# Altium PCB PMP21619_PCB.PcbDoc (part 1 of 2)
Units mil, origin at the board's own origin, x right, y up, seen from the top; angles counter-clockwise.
Board outline 3937.01 x 3937.01 mil, 8 copper layers (Top Layer, Signal Layer 1, Signal Layer 2, Signal Layer 3, Signal Layer 4, Signal Layer 5, Signal Layer 6, Bottom Layer), stack 62.283 mil thick; 227 components, 41 nets, 547 pads, 421 vias.
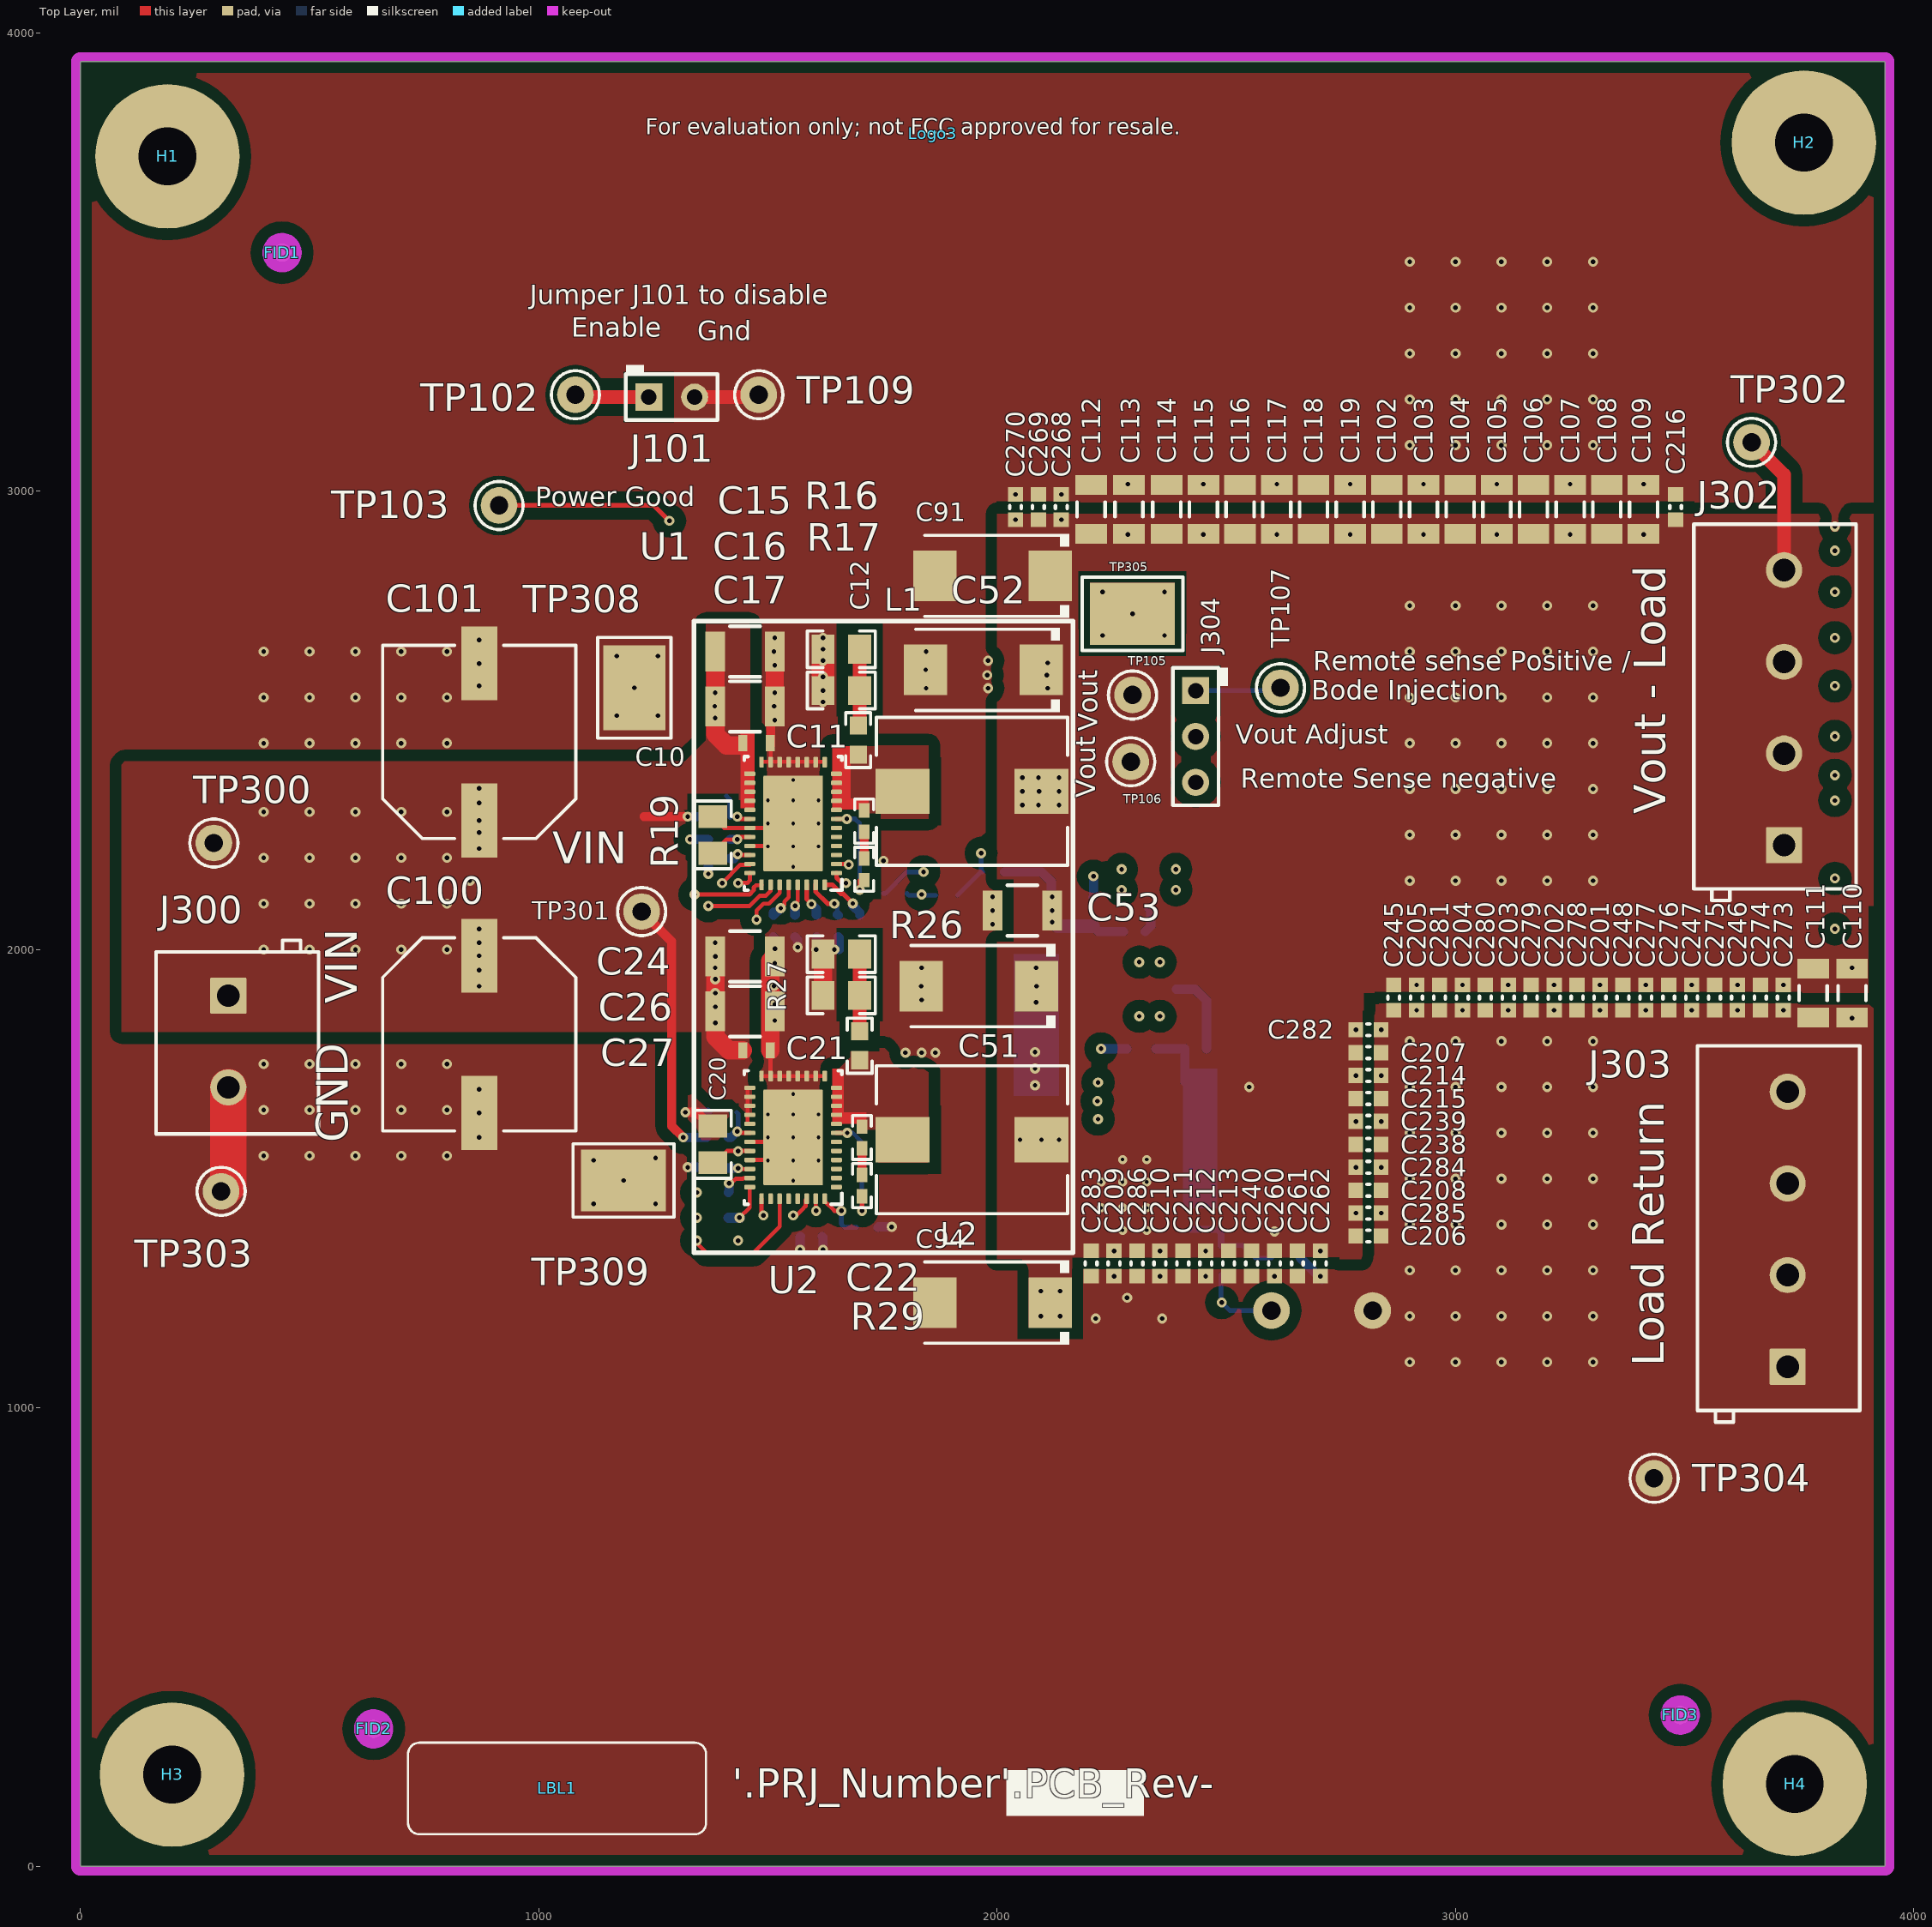
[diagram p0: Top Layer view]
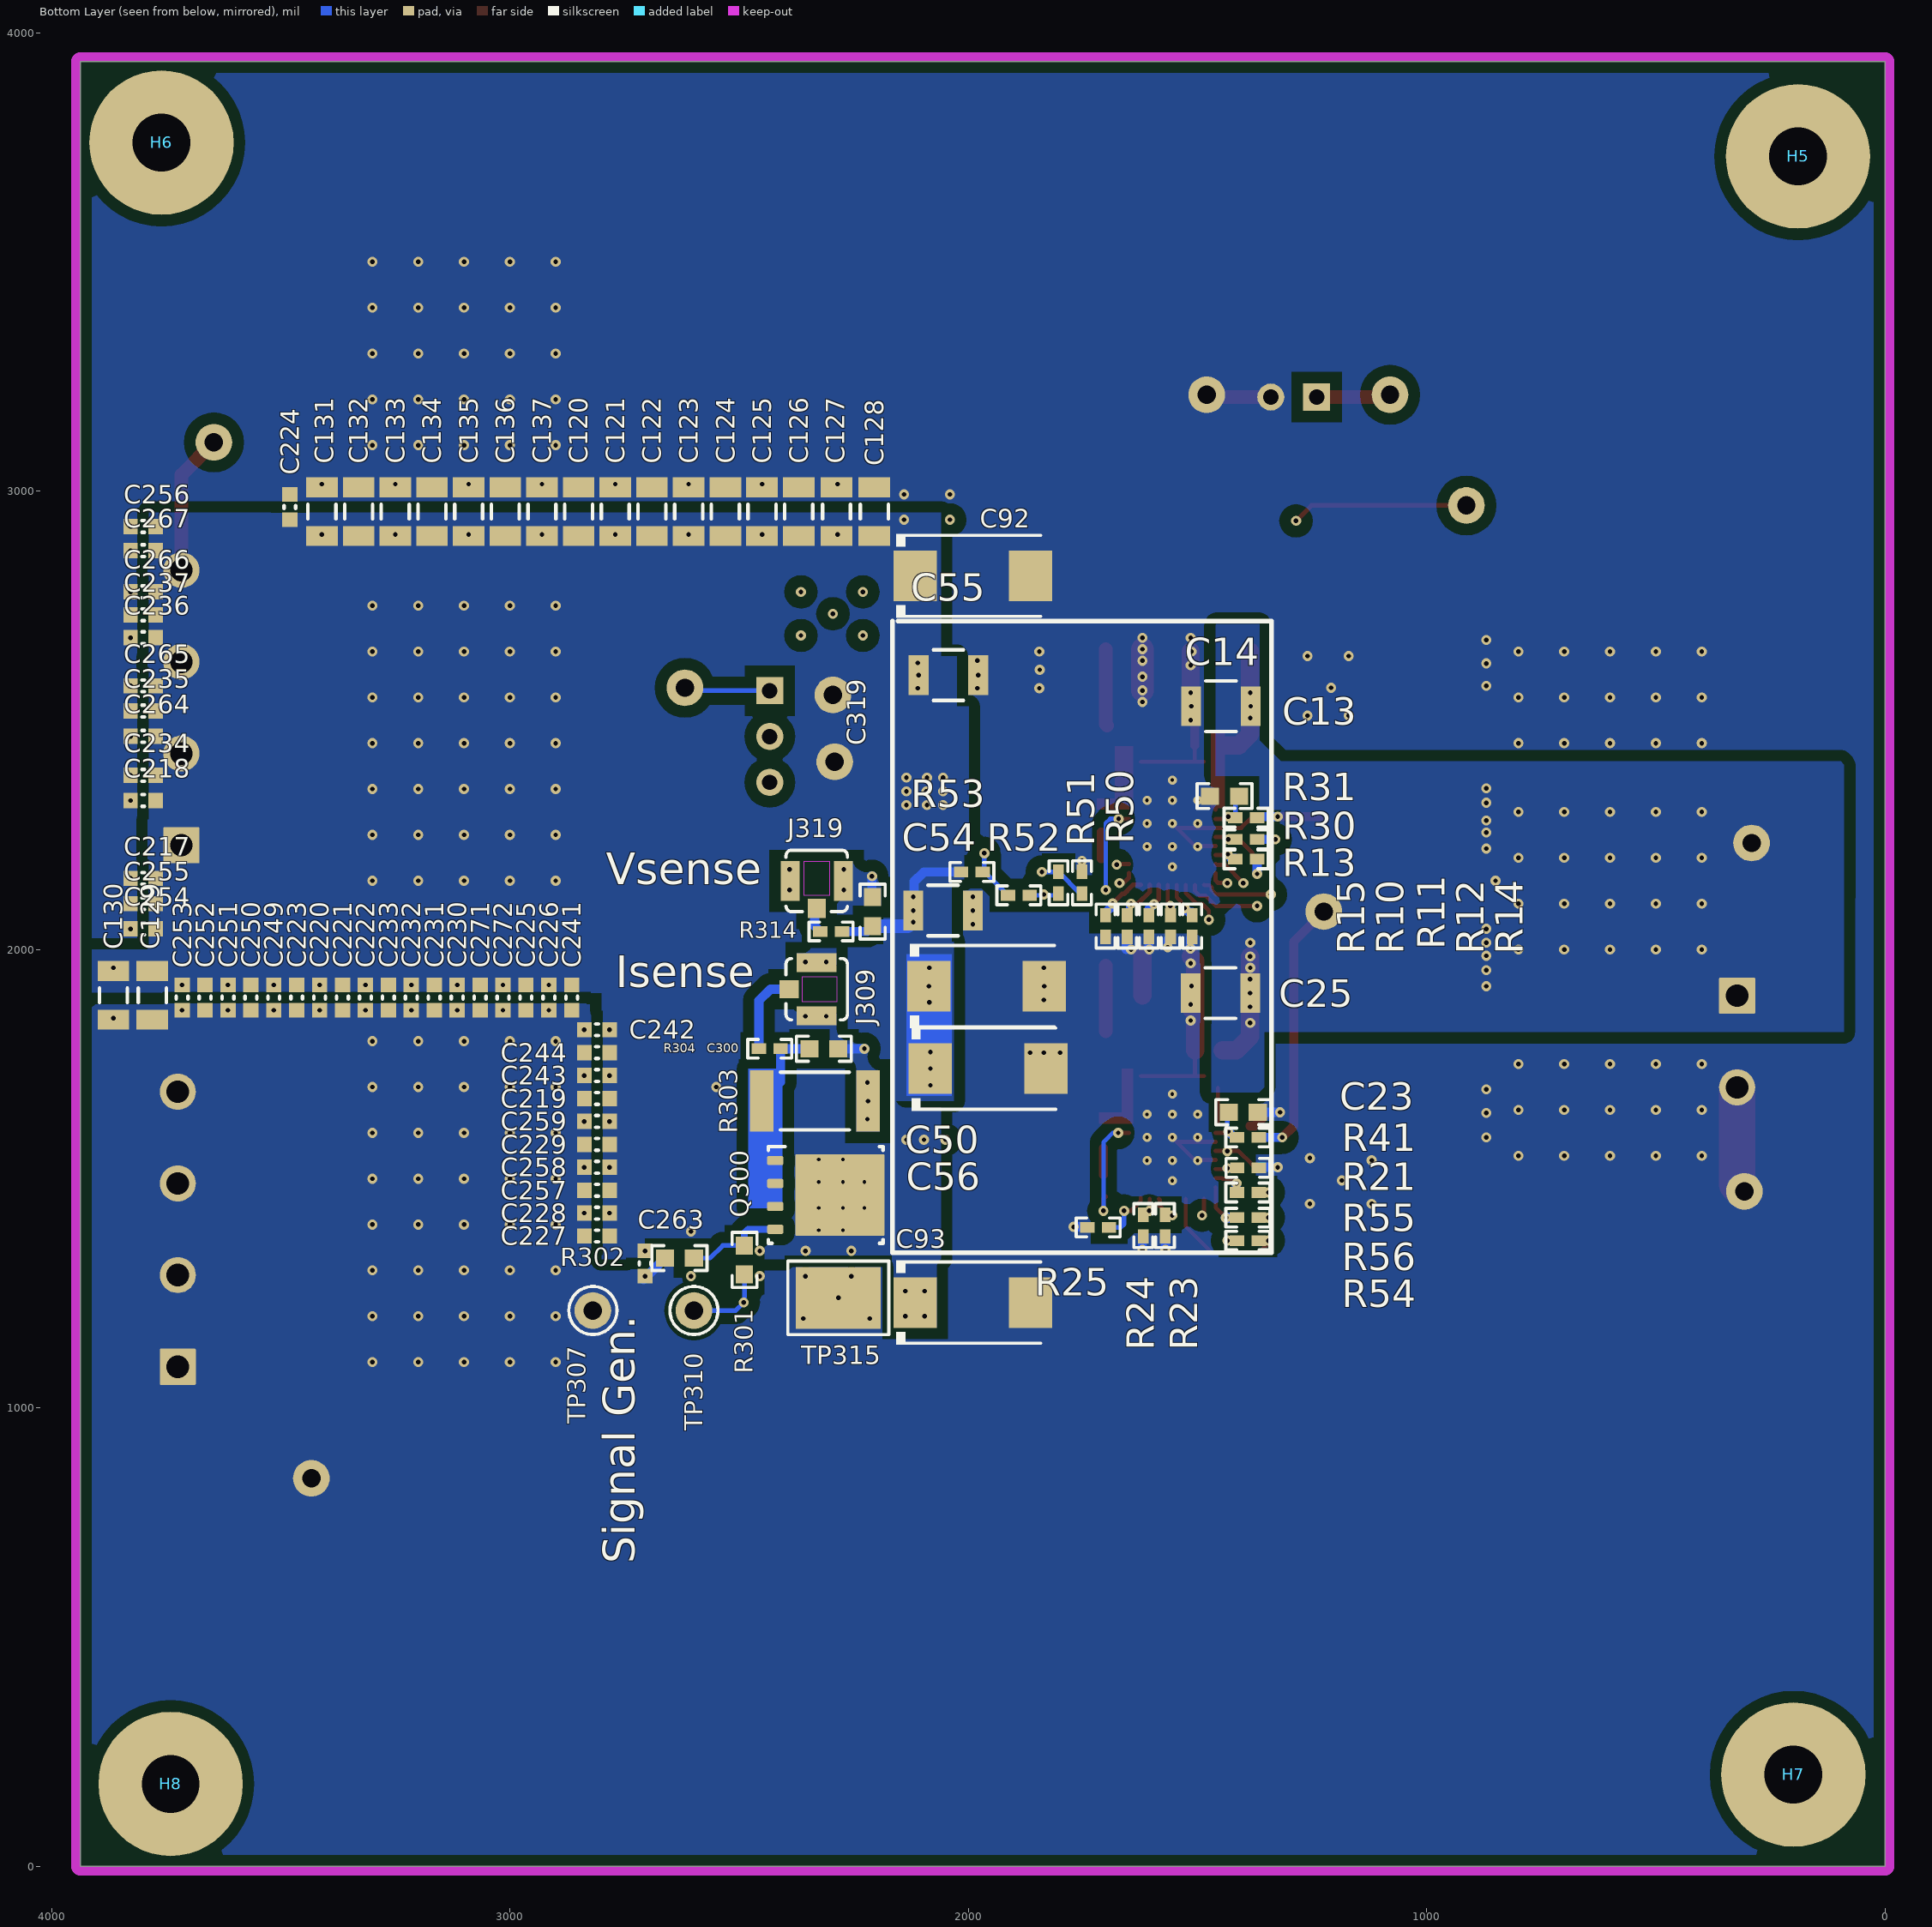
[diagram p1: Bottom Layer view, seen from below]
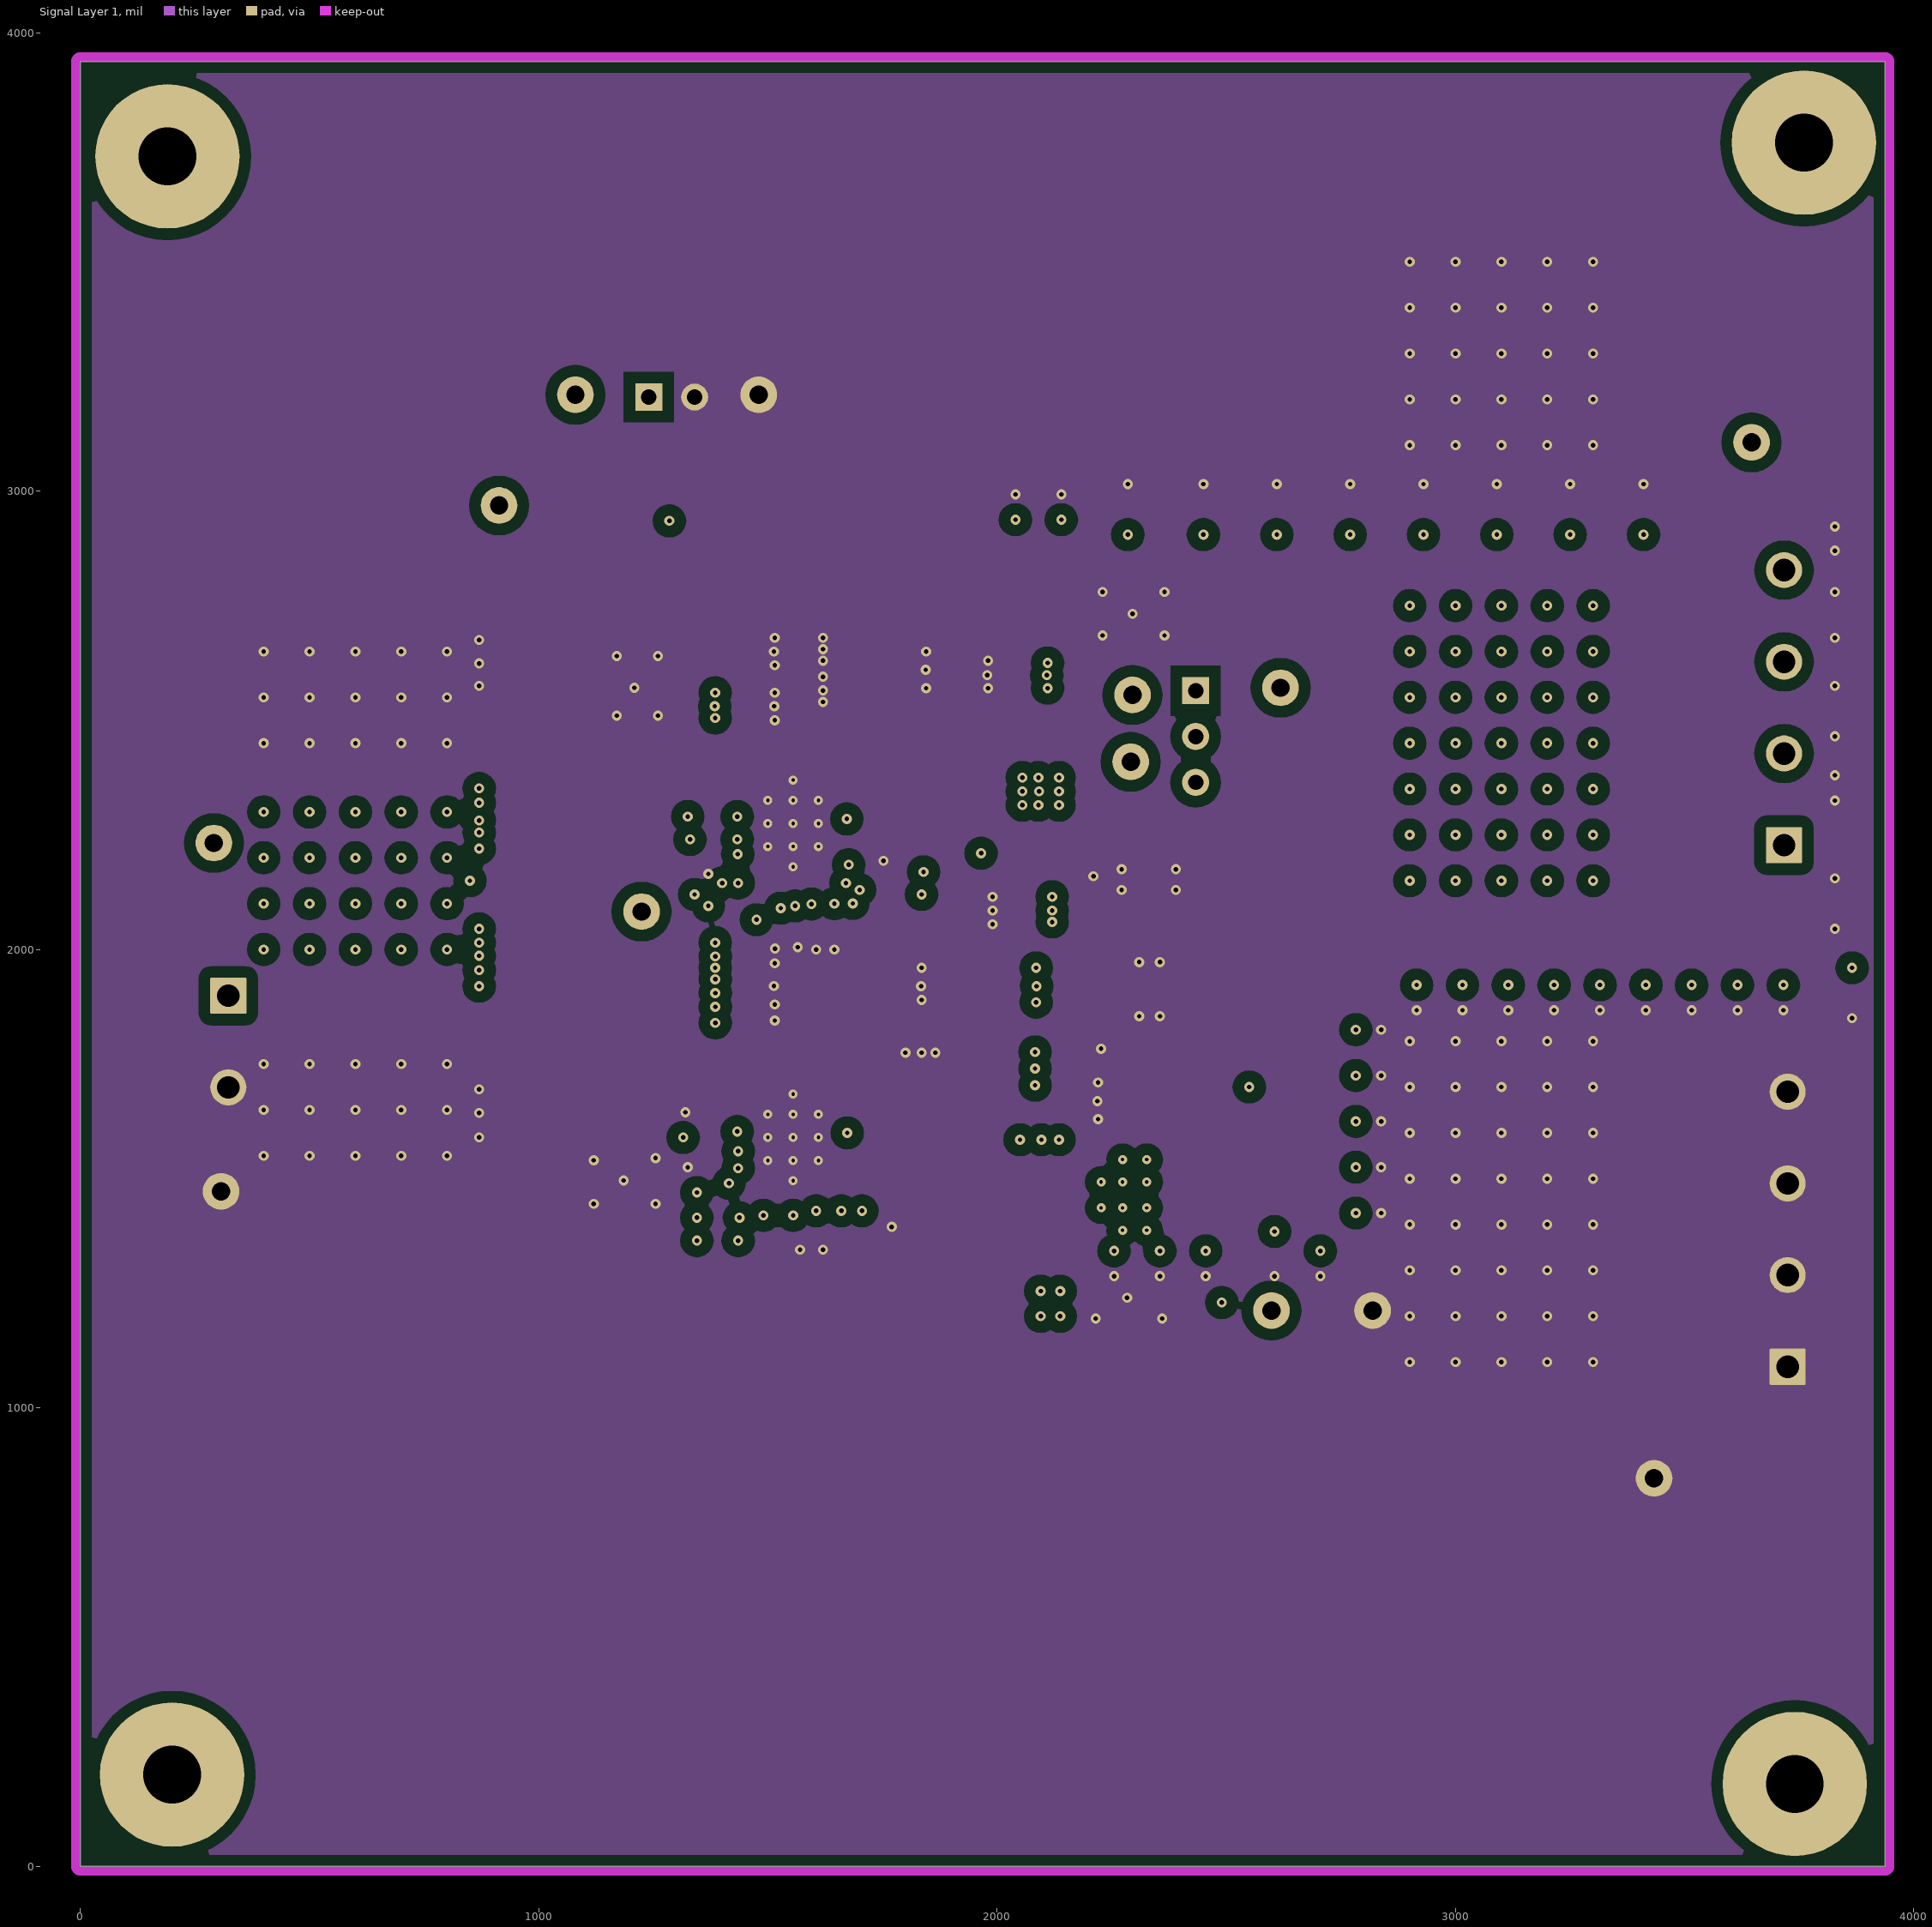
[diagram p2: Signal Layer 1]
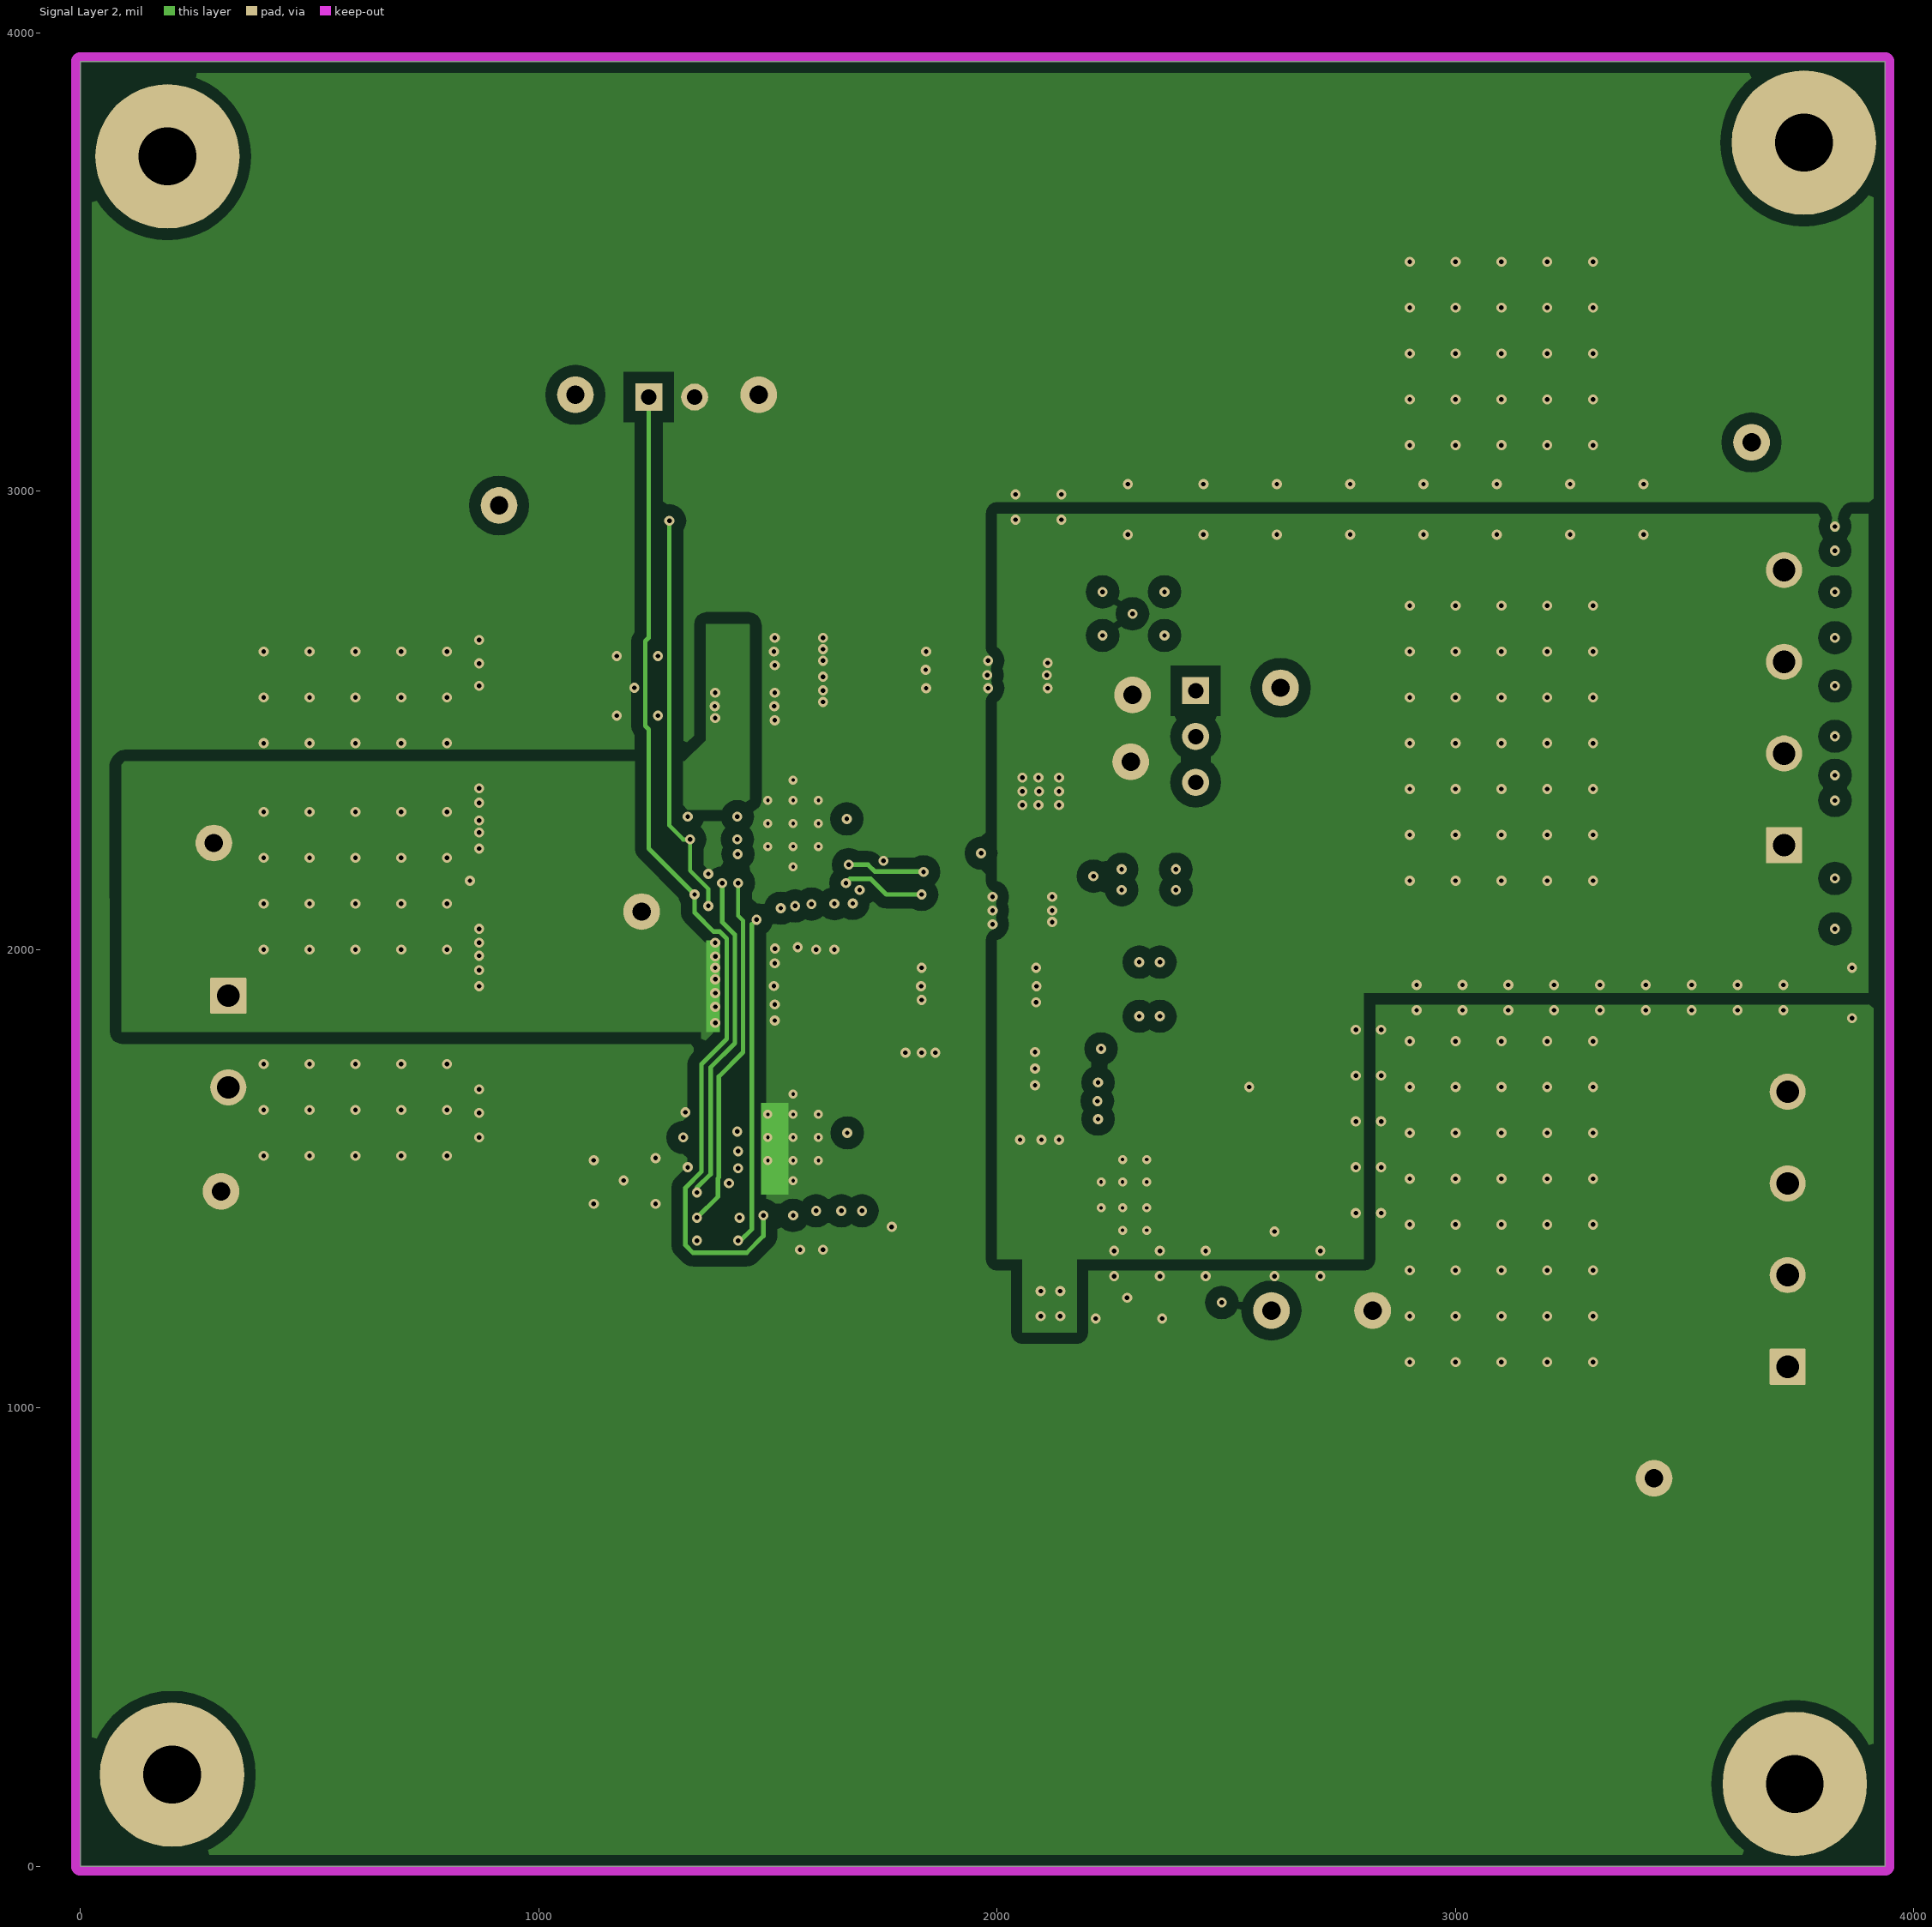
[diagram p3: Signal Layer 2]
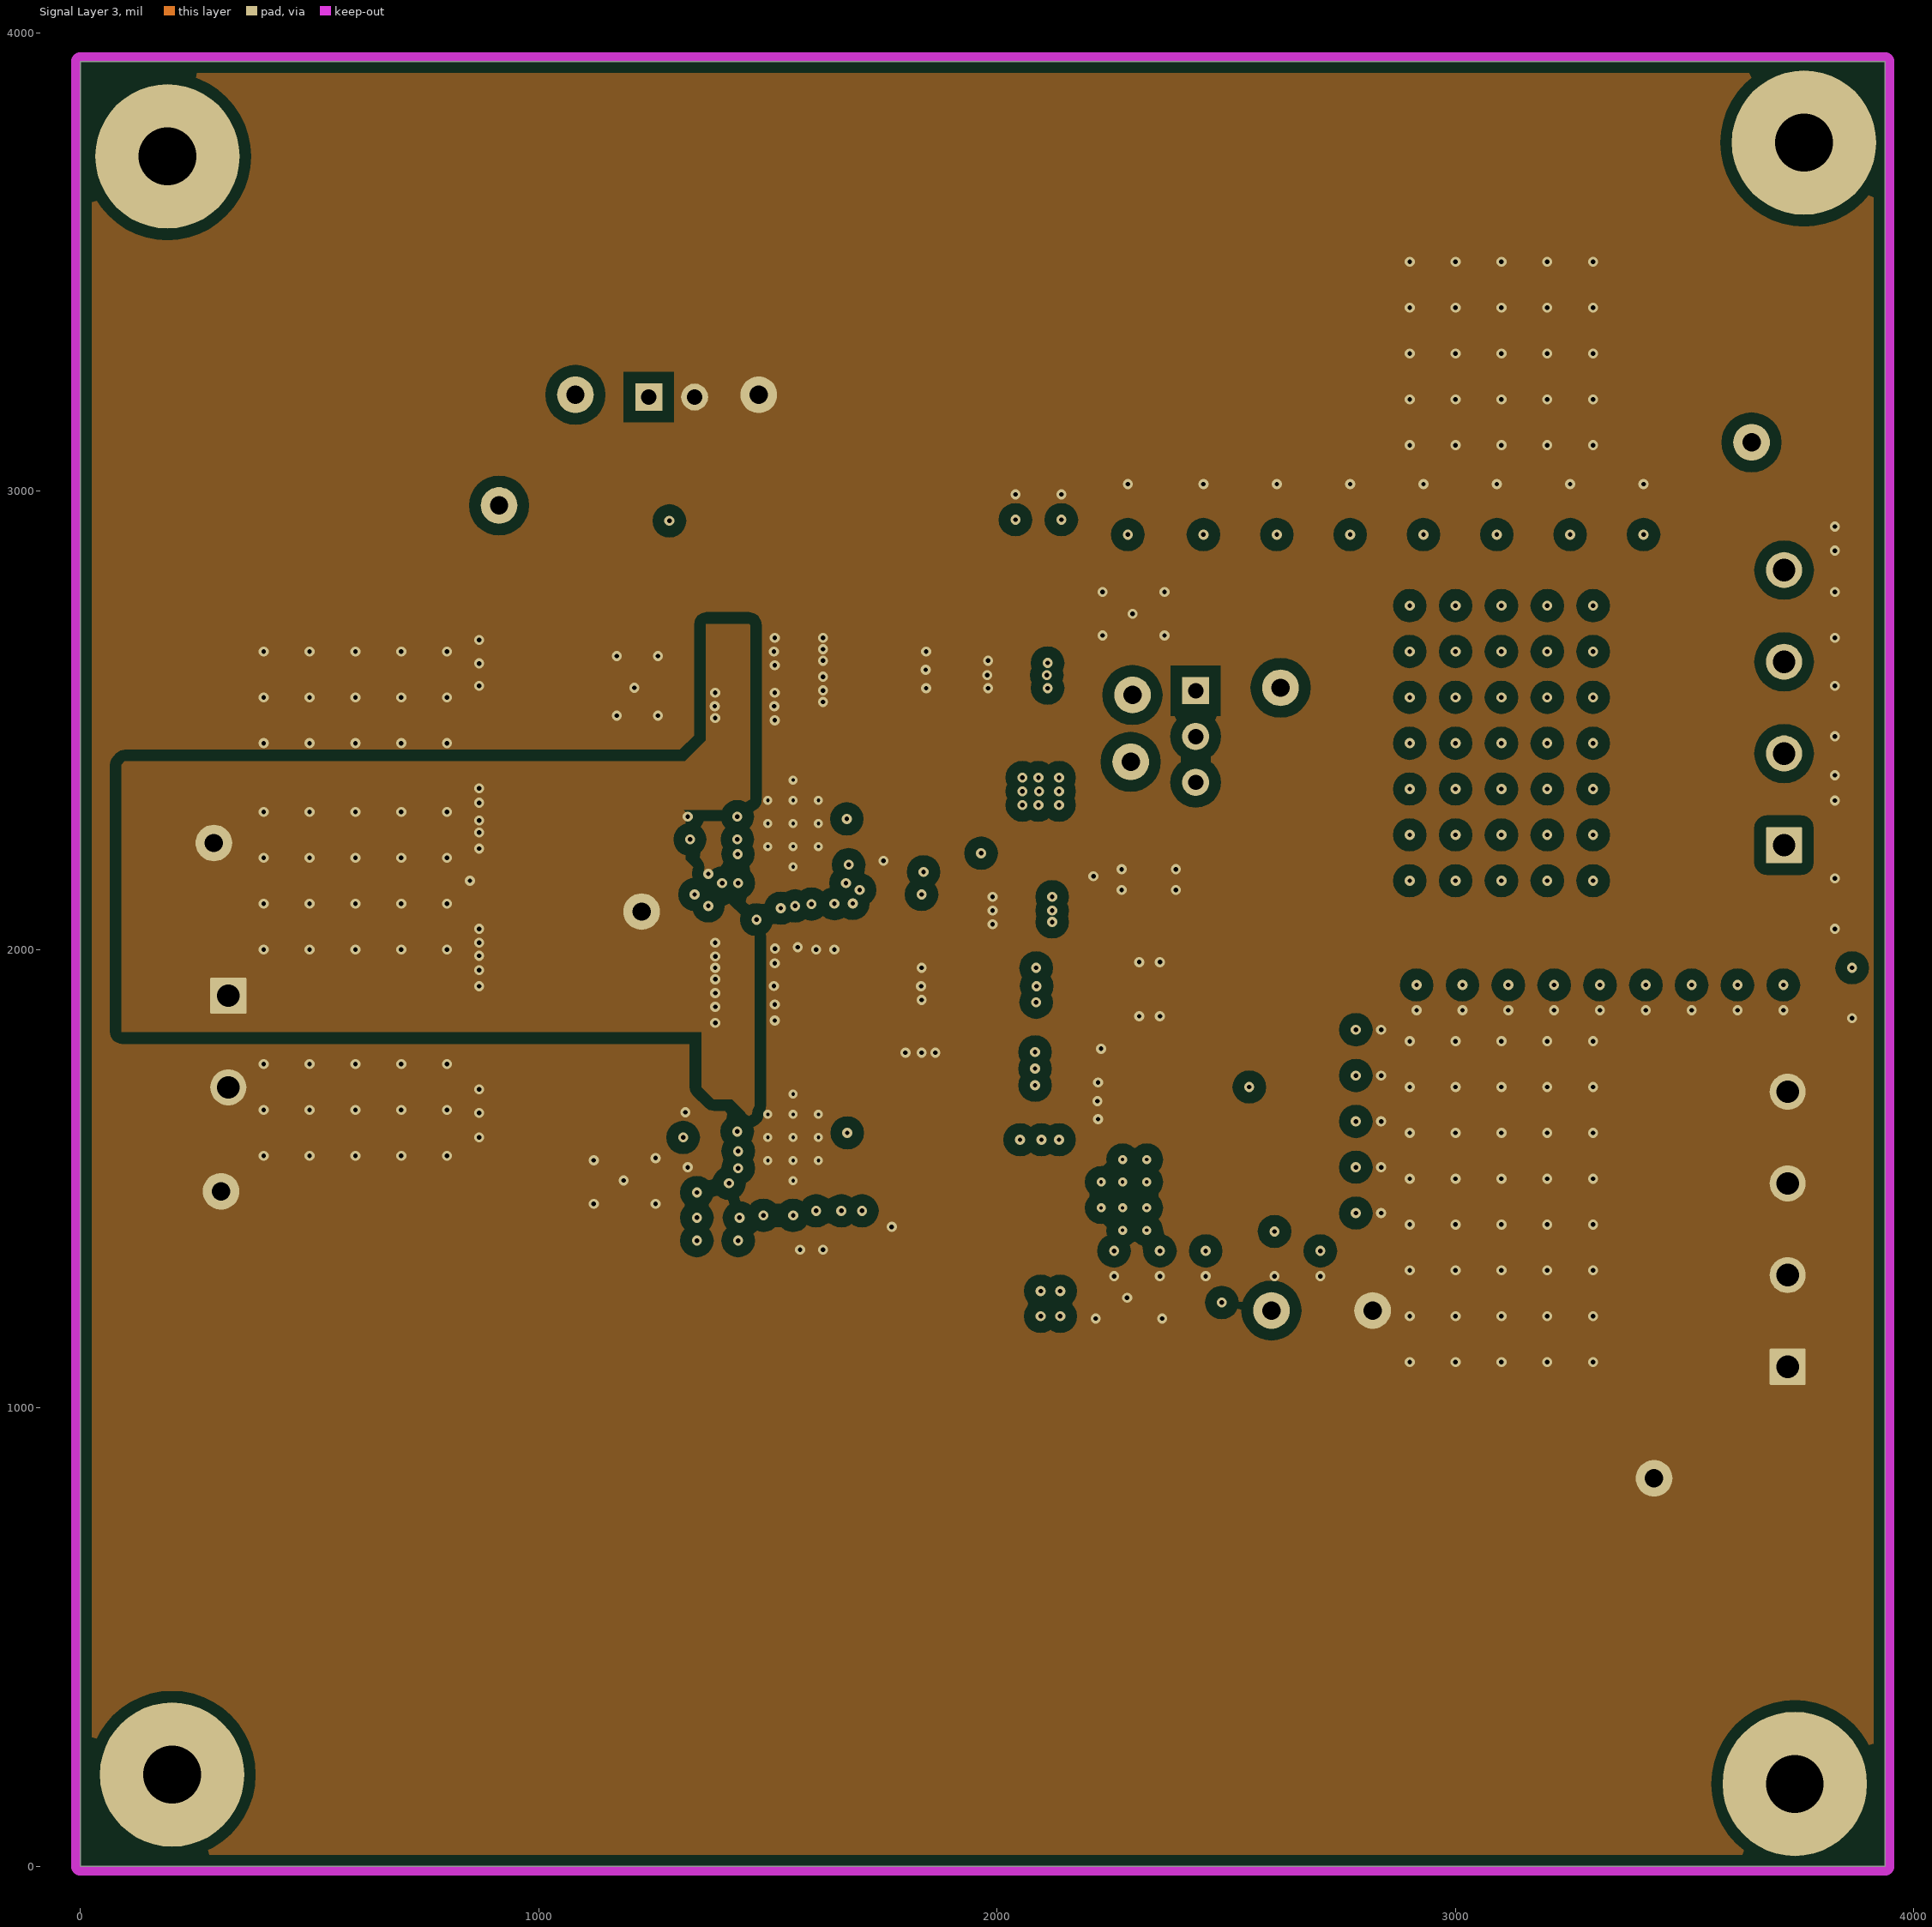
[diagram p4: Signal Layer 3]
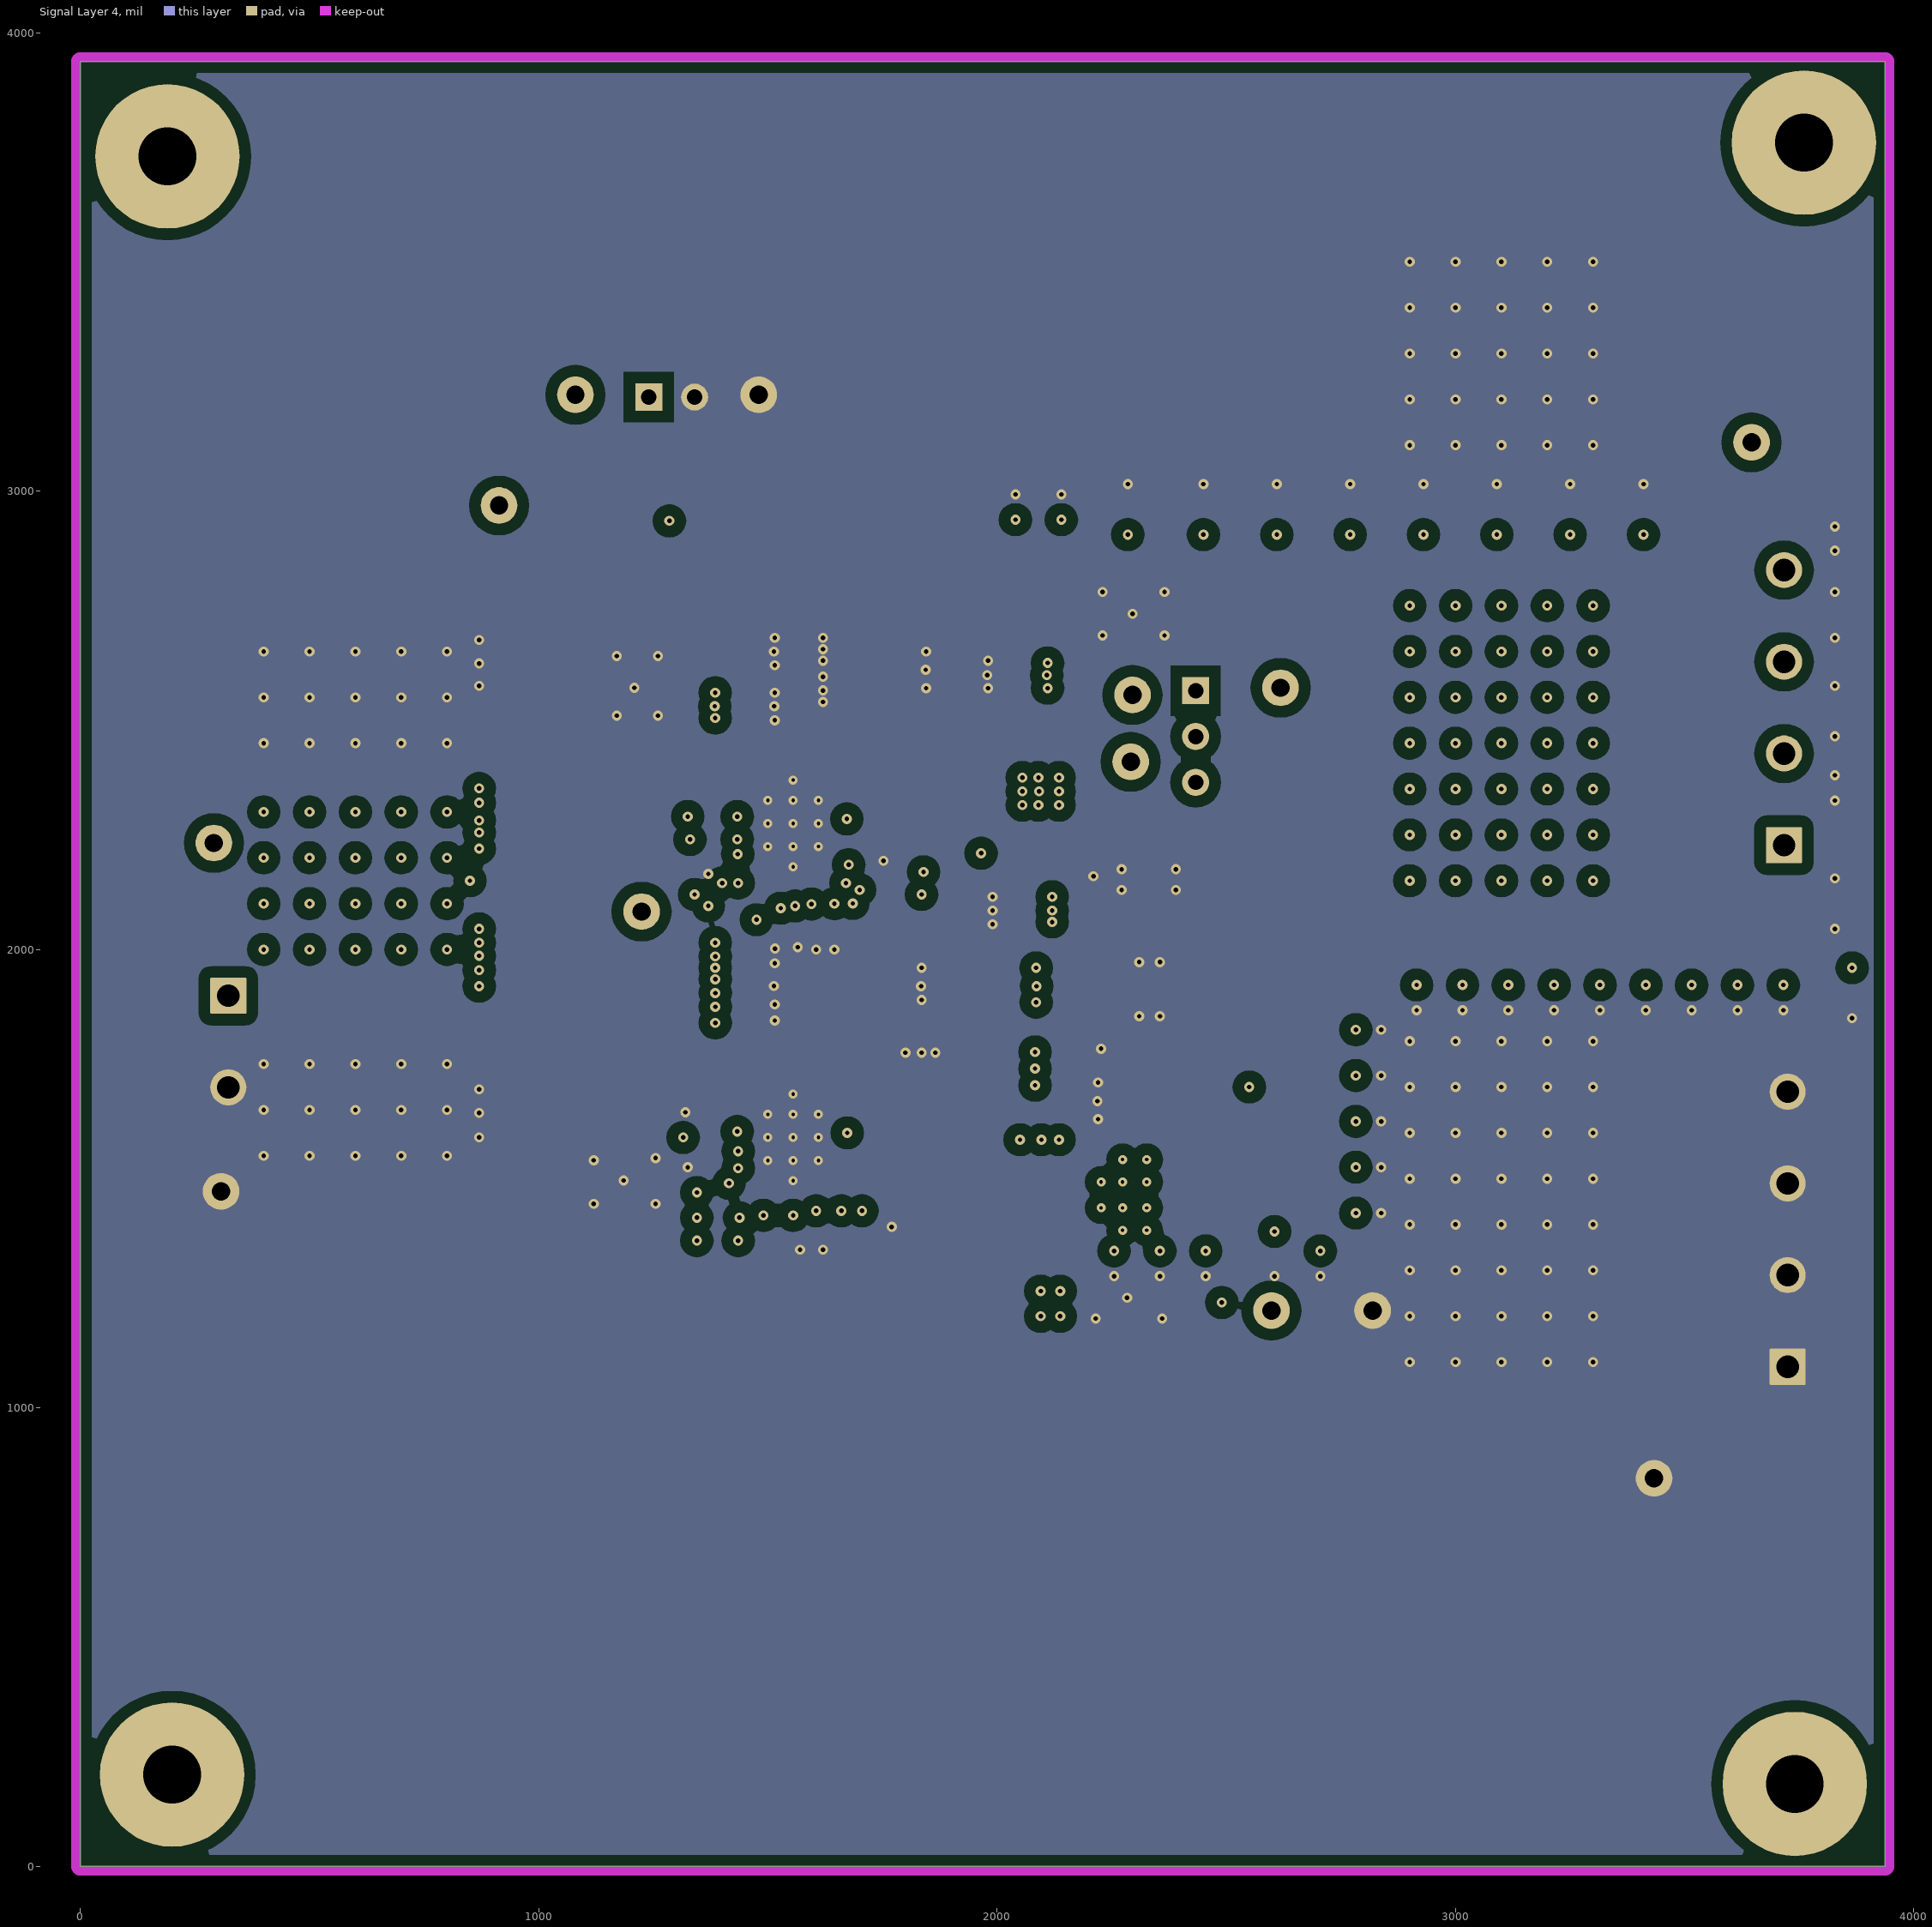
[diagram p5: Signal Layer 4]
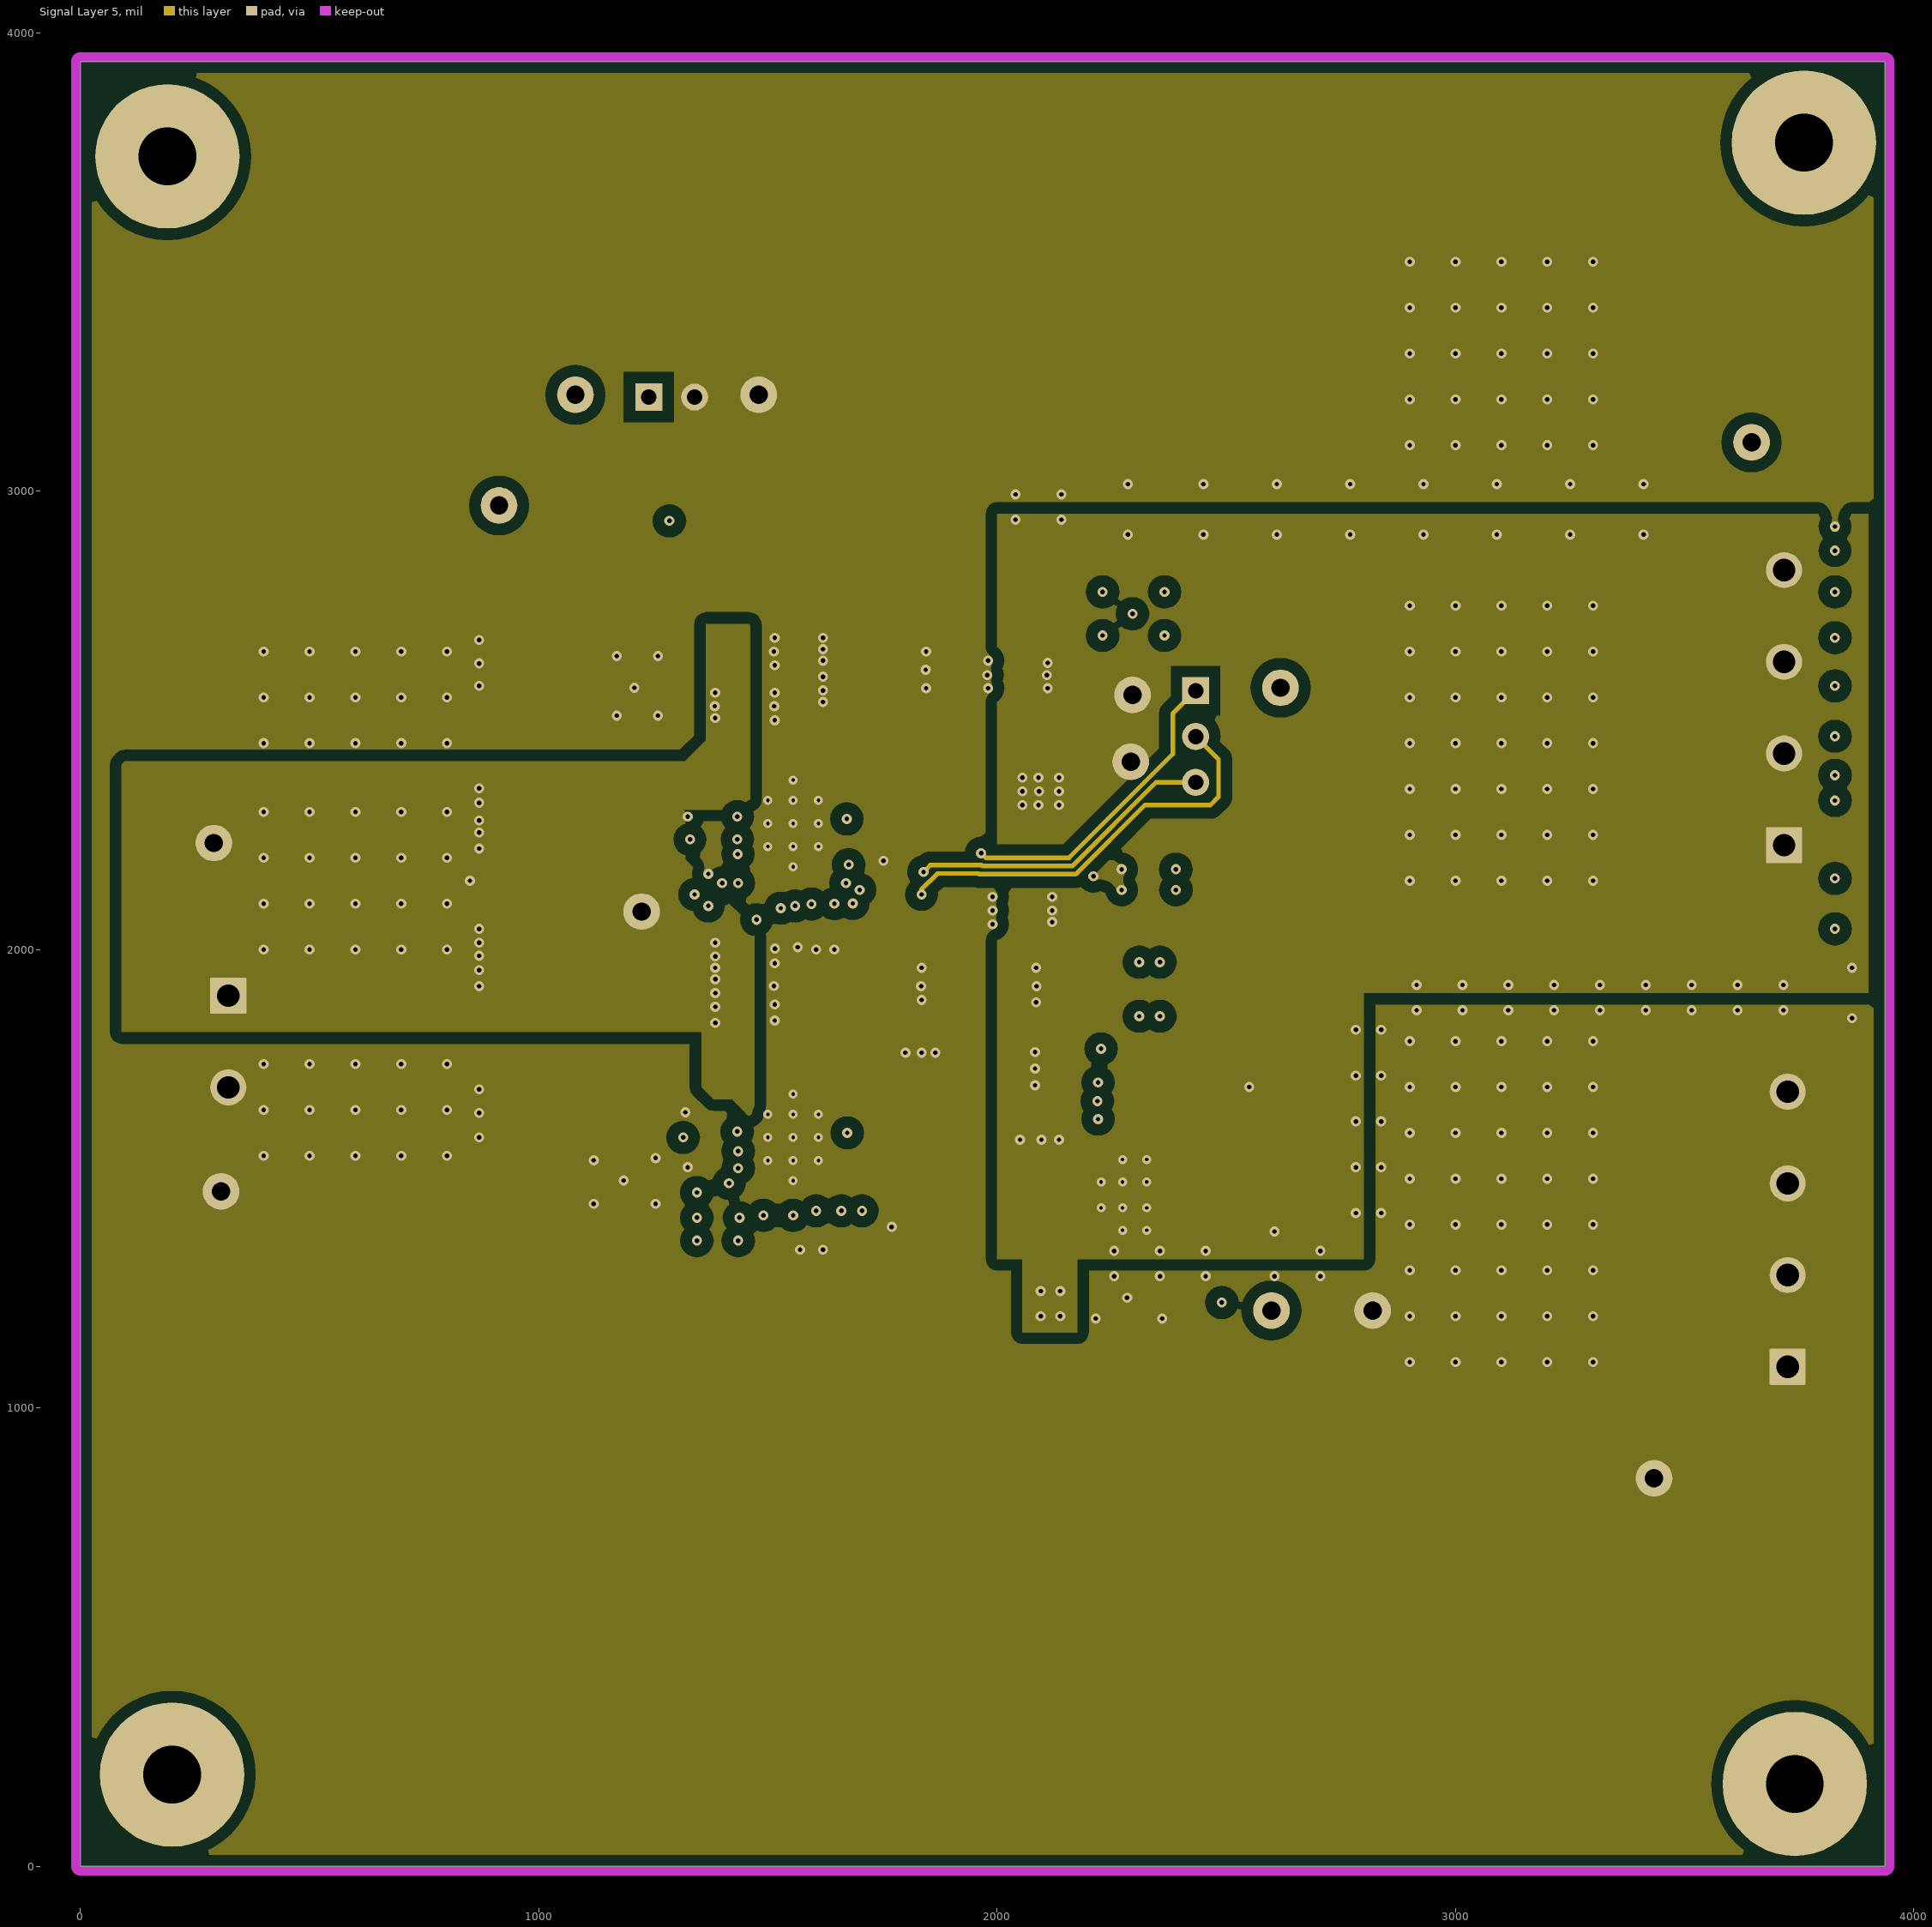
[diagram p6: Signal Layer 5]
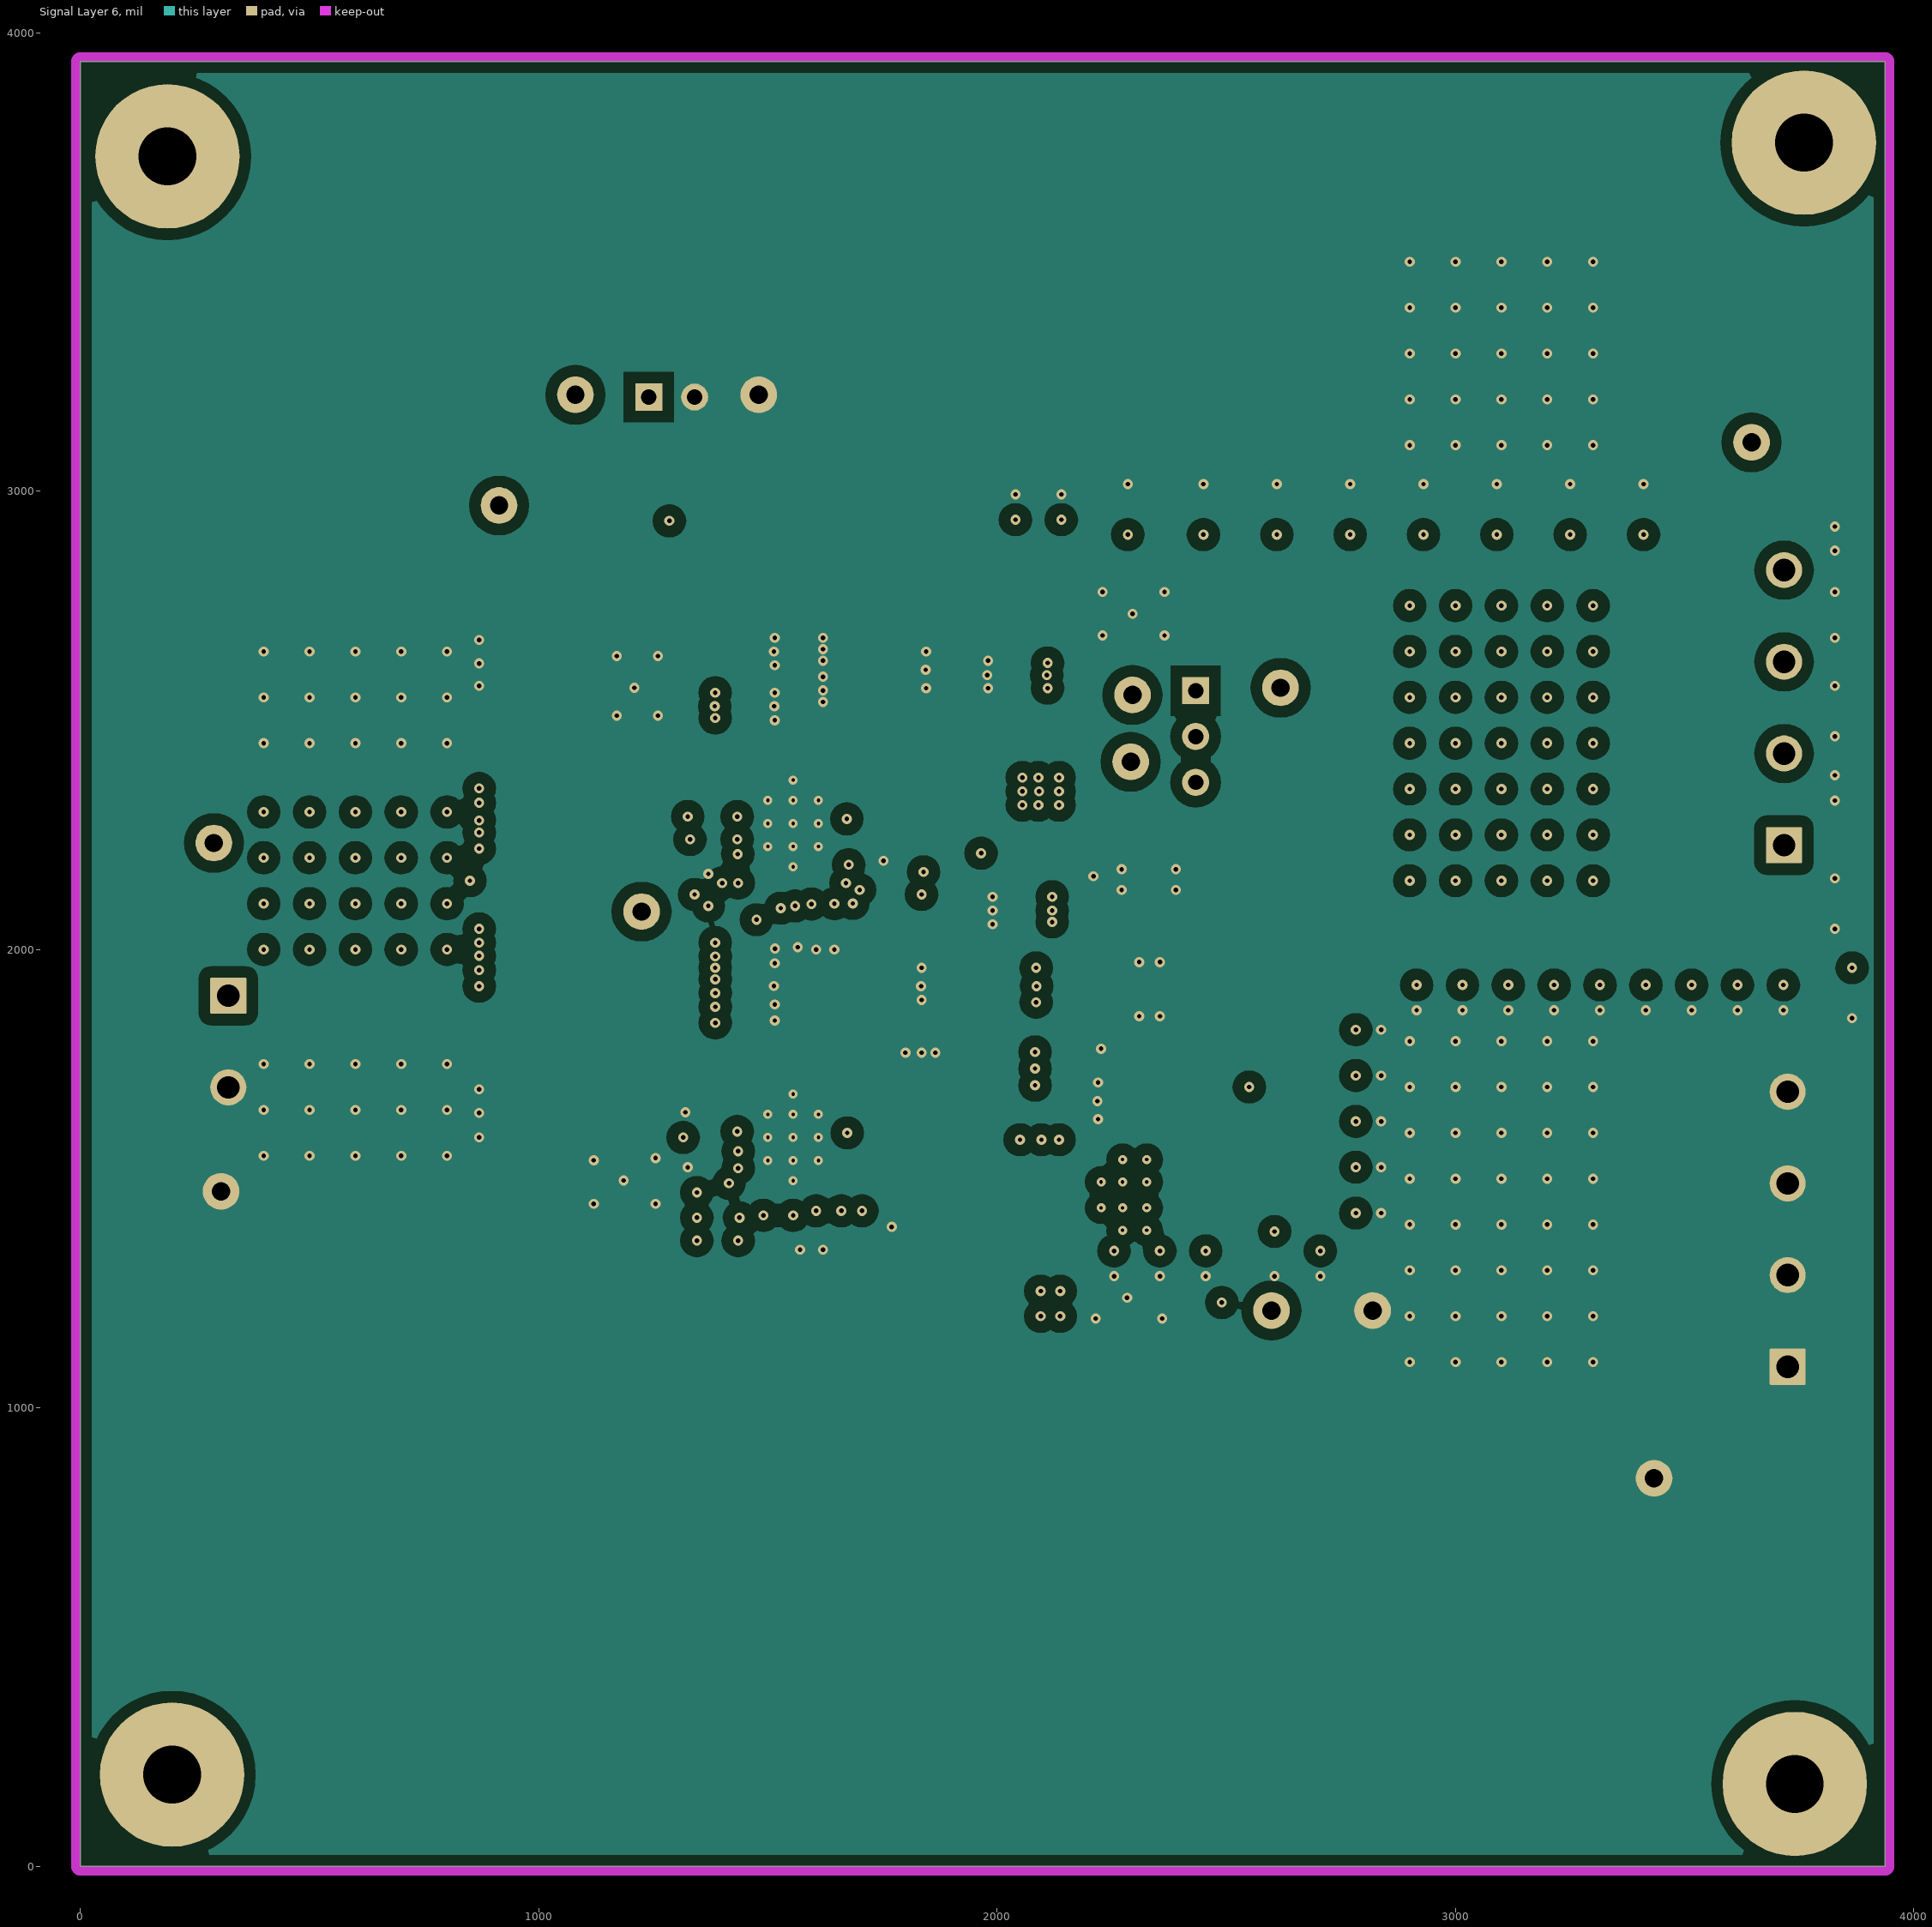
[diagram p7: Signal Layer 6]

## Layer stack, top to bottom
Top Solder: solder mask 0.4, Solder Resist, Dk 3.5
Top Layer: signal copper 2.0866
Dielectric1: core 5.9055, FR-4, Dk 4.8
Signal Layer 1: signal copper 2.7953
Dielectric 2: dielectric 5.9055, Dk 4.2
Signal Layer 2: signal copper 2.7953
Dielectric 3: dielectric 5.9055, Dk 4.2
Signal Layer 3: signal copper 2.7953
Dielectric 4: dielectric 5.9055, Dk 4.2
Signal Layer 4: signal copper 2.7953
Dielectric 5: dielectric 5.9055, Dk 4.2
Signal Layer 5: signal copper 2.7953
Dielectric 6: dielectric 5.9055, Dk 4.2
Signal Layer 6: signal copper 2.7953
Dielectric 7: dielectric 5.9055, Dk 4.2
Bottom Layer: signal copper 2.0866
Bottom Solder: solder mask 0.4, Solder Resist, Dk 3.5

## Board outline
0,0 3937.01,0 3937.01,3937.01 0,3937.01

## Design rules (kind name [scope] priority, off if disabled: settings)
AcuteAngle [All] p1: minimum=4.50000000000000E+0001 checktracksonly=FALSE
AssemblyTestPointUsage [All] p1: valid=2
BoardOutlineClearance BoardOutlineClearance_MountingHoles [OnCopper and InComponentClass('Mounting Holes')] p1: gap=40 ignorepadtopadclearanceinfootprint=FALSE
BoardOutlineClearance BoardOutlineClearance_Poly [OnCopper and IsPoly] p2: gap=25 ignorepadtopadclearanceinfootprint=FALSE
BoardOutlineClearance [OnCopper and Not InComponentClass('Logo') and not InComponentClass('FiducialMark') and not InRegion(1000,500,4000,800) and not InPoly] p3: gap=75 ignorepadtopadclearanceinfootprint=FALSE
Clearance Clearance_Keepouts [((IsTrack Or IsArc) And Not InPoly) And IsFree and IsKeepOut vs ((IsTrack Or IsArc) And Not InPoly) And IsFree and IsKeepOut] p1: gap=0 ignorepadtopadclearanceinfootprint=FALSE
Clearance Clearance_Poly [InPolygon] p2: gap=25 ignorepadtopadclearanceinfootprint=FALSE except(0: Arc-Hole Track-Hole SMDPad-Hole THPad-Hole Via-Hole Fill-Hole Poly-Hole Region-Hole Text-Hole)
Clearance [All] p3: gap=7.87 ignorepadtopadclearanceinfootprint=FALSE except(0: Arc-Hole Track-Hole SMDPad-Hole THPad-Hole Via-Hole Fill-Hole Poly-Hole Region-Hole Text-Hole)
ComponentClearance ComponentClearance_MountingHoles_FiducialMarks [InComponentClass('Mounting Holes') vs InComponentClass('FiducialMark')] p1: gap=50 collisioncheckmode=3 verticalgap=10 showdistances=FALSE
ComponentClearance ComponentClearance_Shunt [InComponentClass('Header') vs InComponentClass('Shunt')] p2: gap=0 collisioncheckmode=3 verticalgap=0 showdistances=FALSE
ComponentClearance ComponentClearance_Logo [InComponentClass('Logo')] p3: gap=50 collisioncheckmode=3 verticalgap=10 showdistances=FALSE
ComponentClearance ComponentClearance_ScrewToNut [(HasFootprint('NY PMS 440 0025 PH')) vs (HasFootprint('Keystone_1902C'))] p4: gap=5 collisioncheckmode=3 verticalgap=10 showdistances=FALSE
ComponentClearance ComponentClearance_MountingHoles [InComponentClass('Mounting Holes')] p5: gap=250 collisioncheckmode=3 verticalgap=100000 showdistances=FALSE
ComponentClearance ComponentClearance_SmallPassives [HasFootprint('0201*') or HasFootprint('0402*') or HasFootprint('0508') or HasFootprint('0603*') or HasFootprint('0612') or HasFootprint('0805*') or HasFootprint('0815*') or HasFootprint('0830*') or HasFootprint('1206*') or HasFootprint('1210*') or HasFootprint('1808*') or HasFootprint('1812*') or HasFootprint('1825*') or HasFootprint('2010*') or HasFootprint('2220*') or HasFootprint('2225*') or HasFootprint('2512*') or HasFootprint('2728*') or HasFootprint('3518*') vs HasFootprint('0201*') or HasFootprint('0402*') or HasFootprint('0508') or HasFootprint('0603*') or HasFootprint('0612') or HasFootprint('0805*') or HasFootprint('0815*') or HasFootprint('0830*') or HasFootprint('1206*') or HasFootprint('1210*') or HasFootprint('1808*') or HasFootprint('1812*') or HasFootprint('1825*') or HasFootprint('2010*') or HasFootprint('2220*') or HasFootprint('2225*') or HasFootprint('2512*') or HasFootprint('2728*') or HasFootprint('3518*')] p6: gap=14.96 collisioncheckmode=3 verticalgap=10 showdistances=FALSE
ComponentClearance ComponentClearance_THtoSMT [IsThruComponent vs IsSMTComponent] p7: gap=40 collisioncheckmode=3 verticalgap=30 showdistances=FALSE
ComponentClearance ComponentClearance_THtoTH [IsThruComponent vs IsThruComponent] p8: gap=30 collisioncheckmode=3 verticalgap=30 showdistances=FALSE
ComponentClearance [All] p9: gap=30 collisioncheckmode=3 verticalgap=10 showdistances=FALSE
DiffPairsRouting [All] p1: maxlimit=100 minlimit=10 mostfreqgap=10 toplayer_minwidth=15 toplayer_maxwidth=15 toplayer_prefwidth=15 midlayer1_minwidth=15 midlayer1_maxwidth=15 midlayer1_prefwidth=15 midlayer2_minwidth=15 midlayer2_maxwidth=15 midlayer2_prefwidth=15 midlayer3_minwidth=15 midlayer3_maxwidth=15 midlayer3_prefwidth=15 midlayer4_minwidth=15 midlayer4_maxwidth=15 midlayer4_prefwidth=15 midlayer5_minwidth=15 midlayer5_maxwidth=15 midlayer5_prefwidth=15 midlayer6_minwidth=15 midlayer6_maxwidth=15 midlayer6_prefwidth=15 bottomlayer_minwidth=15 bottomlayer_maxwidth=15 bottomlayer_prefwidth=15 maxuncoupledlength=1000
FabricationTestPointUsage TestPointUsage [All] p1: valid=2 allowmultiple=FALSE
FabricationTestpoint Testpoint [All] p1: side=3 testpointundercomponent=TRUE minsize=40 maxsize=100 preferedsize=60 minholesize=0 maxholesize=40 preferedholesize=32 testpointgrid=1 allowsidetop=TRUE allowsidebottom=TRUE usegrid=TRUE gridtolerance=0.01
FanoutControl Fanout_LCC [IsLCC] p1: bgadir=Out bgaviamode=Centered fanoutstyle=Auto fanoutdirection=Alternating viagrid=1 // Fanout_LCC (Default Rule)
FanoutControl Fanout_BGA [IsBGA] p2: bgadir=Out bgaviamode=Centered fanoutstyle=Auto fanoutdirection=Alternating viagrid=1 // Fanout_BGA (Default Rule)
FanoutControl Fanout_Default [All] p4: bgadir=Out bgaviamode=Centered fanoutstyle=Auto fanoutdirection=Alternating viagrid=1 // Fanout_Default (Default Rule)
FanoutControl Fanout_Small [(CompPinCount < 5)] p5: bgadir=Out bgaviamode=Centered fanoutstyle=Auto fanoutdirection=OutThenIn viagrid=1 // Fanout_Small (Default Rule)
HoleSize [All] p1: absolutevalues=TRUE maxlimit=251 minlimit=7.87 maxpercent=80.000 minpercent=20.000
MinimumAnnularRing MinimumAnnularRing_ThermalPadVias [IsVia and InAnyComponent] p1: minimumring=5.91
MinimumAnnularRing [All] p2: minimumring=6
MinimumSolderMaskSliver MinimumSolderMaskSliver_Logo [InComponentClass('Logo') vs InComponentClass('Logo')] p1: minsoldermaskwidth=0.7
MinimumSolderMaskSliver [All] p2: minsoldermaskwidth=3.94
PlaneConnect [All] p1: planeconnectstyle=Relief reliefexpansion=10 reliefentries=4 reliefconductorwidth=10 reliefairgap=10
PolygonConnect [All] p1: connectstyle=Direct reliefconductorwidth=10 reliefentries=4 polygonreliefangle="90 Angle" airgapwidth=10
RoutingVias ThermalPadVias [IsVia and InAnyComponent] p1: holewidth=7.87 width=19.68 viastyle="Through Hole" minholewidth=7.87 minwidth=19.68 maxholewidth=12.99 maxwidth=23.62
RoutingVias [All] p2: holewidth=16 width=34 viastyle="Through Hole" minholewidth=7.87 minwidth=20 maxholewidth=40 maxwidth=65
SilkToBoardRegionClearance [Not ((IsComment or IsDesignator) And (Hide <> 'False')) and not InRegion(1000,500,4000,800)] p1:
SilkToSilkClearance SilkToSilkClearance_Pb-FreeLogo [(HasFootprint('Pb-Free_Overlay_Medium') OR HasFootprint('Pb-Free_Overlay_Small')) vs (HasFootprint('Pb-Free_Overlay_Medium') OR HasFootprint('Pb-Free_Overlay_Small'))] p1: silktosilkclearance=0
SilkToSilkClearance [All] p2: silktosilkclearance=4
SilkToSolderMaskClearance SilkToComponentPadClearance [(IsPad or IsFill or IsRegion) and InAnycomponent] p1: minsilkscreentomaskgap=5 clearancetoexposedcopper=TRUE
SilkToSolderMaskClearance "Silk to Solder Mask Opening" [All] p2: minsilkscreentomaskgap=4 clearancetoexposedcopper=FALSE
SolderMaskExpansion [All] p1: expansion=1.97
Width [All] p1: maxlimit=100 minlimit=6 preferedwidth=10 checkconnectedcopper=TRUE
15 further rules are at their usual default settings.

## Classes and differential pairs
component class "Mounting Holes": H1 H2 H3 H4
component class PMP21619_Caps&Hardware: C91 C92 C93 C94 C102 C103 C104 C105 C106 C107 C108 C109 C110 C111 C112 C113 C114 C115 C116 C117 C118 C119 C120 C121 C122 C123 C124 C125 C126 C127 C128 C129 C130 C131 C132 C133 C134 C135 C136 C137 C201 C202 C203 C204 C205 C206 C207 C208 C209 C210 C211 C212 C213 C214 C215 C216 C217 C218 C219 C220 C221 C222 C223 C224 C225 C226 C227 C228 C229 C230 C231 C232 C233 C234 C235 C236 C237 C238 C239 C240 C241 C242 C243 C244 C245 C246 C247 C248 C249 C250 C251 C252 C253 C254 C255 C256 C257 C258 C259 C260 C261 C262 C263 C264 C265 C266 C267 C268 C269 C270 C271 C272 C273 C274 C275 C276 C277 C278 C279 C280 C281 C282 C283 C284 C285 C286 FID1 FID2 FID3 H1 H2 H3 H4 H5 H6 H7 H8 LBL1 Logo3 ZZ1
component class FiducialMark: FID1 FID2 FID3
component class AssemblyNote: ZZ1
component class Label: LBL1
component class Header: J101 J304
component class PMP21619_2phaseDCDC: C10 C11 C12 C13 C14 C15 C16 C17 C20 C21 C22 C23 C24 C25 C26 C27 C50 C51 C52 C53 C54 C55 C56 C100 C101 C300 C319 J101 J300 J302 J303 J304 J309 J319 L1 L2 Q300 R10 R11 R12 R13 R14 R15 R16 R17 R19 R21 R23 R24 R25 R26 R27 R29 R30 R31 R41 R50 R51 R52 R53 R54 R55 R56 R301 R302 R303 R304 R314 TP102 TP103 TP105 TP106 TP107 TP109 TP300 TP301 TP302 TP303 TP304 TP305 TP307 TP308 TP309 TP310 TP315 U1 U2

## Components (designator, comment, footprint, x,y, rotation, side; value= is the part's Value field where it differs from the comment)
C10 "Capacitor" 0805_HV 1380,2250 r270 top value=4.7uF
C11 "Capacitor" 0603 1696.85,2456.69 r90 top value=1000pF
C12 "Capacitor" 0402 1710,2280 r90 top value=0.1uF
C13 "Capacitor" 0603 1440.94,2334.65 r0 bottom value=1uF
C14 "Capacitor" 1210_280 1448.82,2530.49 r180 bottom value=10uF
C15 "Capacitor" 1210_280 1450,2650 r180 top value=10uF
C16 "Capacitor" 1210_280 1450,2530 r180 top value=10uF
C17 "Capacitor" 0603S 1475,2450 r180 top value=0.1uF
C20 "Capacitor" 0805_HV 1380,1575 r90 top value=4.7uF
C21 "Capacitor" 0603 1700,1790 r90 top value=1000pF
C22 "Capacitor" 0402 1705,1590 r90 top value=0.1uF
C23 "Capacitor" 0603 1400,1645 r180 bottom value=1uF
C24 "Capacitor" 1210_280 1450,1985 r0 top value=10uF
C25 "Capacitor" 1210_280 1450,1905 r0 bottom value=10uF
C26 "Capacitor" 1210_280 1450,1865 r0 top value=10uF
C27 "Capacitor" 0603S 1475,1780 r0 top value=0.1uF
C50 "Cap_Polarized" SP-Cap_Standard 1960,1920 r180 bottom value=470uF
C51 "Cap_Polarized" SP-Cap_Standard 1960,1920 r180 top value=470uF
C52 "Cap_Polarized" SP-Cap_Standard 1970,2610 r180 top value=470uF
C53 "Capacitor" 1210_280 2055,2085 r180 top value=100uF
C54 "Capacitor" 1210_280 2055,2085 r180 bottom value=100uF
C55 "Capacitor" 1210_280 2043.31,2598.43 r180 bottom value=100uF
C56 "Cap_Polarized" SP-Cap_Standard 1956.69,1740.16 r180 bottom value=470uF
C91 "Cap_Polarized" SP-Cap_Standard 1990,2815 r180 top value=470uF
C92 "Cap_Polarized" SP-Cap_Standard 1990,2815 r180 bottom value=470uF
C93 "Cap_Polarized" SP-Cap_Standard 1990,1230 r180 bottom value=470uF
C94 "Cap_Polarized" SP-Cap_Standard 1990,1230 r180 top value=470uF
C100 "Cap_Polarized" SM_RADIAL_G 870.08,1814.96 r270 top value=330uF
C101 "Cap_Polarized" SM_RADIAL_G 870.08,2452.76 r90 top value=330uF
C102 "C3216X5R0J107M160AB" 1206_190L 2850,2960 r90 top value=100uF
C103 "C3216X5R0J107M160AB" 1206_190L 2930,2960 r90 top value=100uF
C104 "C3216X5R0J107M160AB" 1206_190L 3010,2960 r90 top value=100uF
C105 "C3216X5R0J107M160AB" 1206_190L 3090,2960 r90 top value=100uF
C106 "C3216X5R0J107M160AB" 1206_190L 3170,2960 r90 top value=100uF
C107 "C3216X5R0J107M160AB" 1206_190L 3250,2960 r90 top value=100uF
C108 "C3216X5R0J107M160AB" 1206_190L 3330,2960 r90 top value=100uF
C109 "C3216X5R0J107M160AB" 1206_190L 3410,2960 r90 top value=100uF
C110 "C3216X5R0J107M160AB" 1206_190L 3865,1905 r270 top value=100uF
C111 "C3216X5R0J107M160AB" 1206_190L 3780,1905 r270 top value=100uF
C112 "C3216X5R0J107M160AB" 1206_190L 2205,2960 r90 top value=100uF
C113 "C3216X5R0J107M160AB" 1206_190L 2287.38,2960 r90 top value=100uF
C114 "C3216X5R0J107M160AB" 1206_190L 2370,2960 r90 top value=100uF
C115 "C3216X5R0J107M160AB" 1206_190L 2450,2960 r90 top value=100uF
C116 "C3216X5R0J107M160AB" 1206_190L 2530,2960 r90 top value=100uF
C117 "C3216X5R0J107M160AB" 1206_190L 2610,2960 r90 top value=100uF
C118 "C3216X5R0J107M160AB" 1206_190L 2690,2960 r90 top value=100uF
C119 "C3216X5R0J107M160AB" 1206_190L 2770,2960 r90 top value=100uF
C120 "C3216X5R0J107M160AB" 1206_190L 2850,2955 r90 bottom value=100uF
C121 "C3216X5R0J107M160AB" 1206_190L 2770,2955 r90 bottom value=100uF
C122 "C3216X5R0J107M160AB" 1206_190L 2690,2955 r90 bottom value=100uF
C123 "C3216X5R0J107M160AB" 1206_190L 2610,2955 r90 bottom value=100uF
C124 "C3216X5R0J107M160AB" 1206_190L 2530,2955 r90 bottom value=100uF
C125 "C3216X5R0J107M160AB" 1206_190L 2450,2955 r90 bottom value=100uF
C126 "C3216X5R0J107M160AB" 1206_190L 2370,2955 r90 bottom value=100uF
C127 "C3216X5R0J107M160AB" 1206_190L 2287.38,2955 r90 bottom value=100uF
C128 "C3216X5R0J107M160AB" 1206_190L 2205,2955 r90 bottom value=100uF
C129 "C3216X5R0J107M160AB" 1206_190L 3780,1900 r270 bottom value=100uF
C130 "C3216X5R0J107M160AB" 1206_190L 3865,1900 r270 bottom value=100uF
C131 "C3216X5R0J107M160AB" 1206_190L 3410,2955 r90 bottom value=100uF
C132 "C3216X5R0J107M160AB" 1206_190L 3330,2955 r90 bottom value=100uF
C133 "C3216X5R0J107M160AB" 1206_190L 3250,2955 r90 bottom value=100uF
C134 "C3216X5R0J107M160AB" 1206_190L 3170,2955 r90 bottom value=100uF
C135 "C3216X5R0J107M160AB" 1206_190L 3090,2955 r90 bottom value=100uF
C136 "C3216X5R0J107M160AB" 1206_190L 3010,2955 r90 bottom value=100uF
C137 "C3216X5R0J107M160AB" 1206_190L 2930,2955 r90 bottom value=100uF
C201 "C1608X6S1C475K080AC" 0603L 3315,1895 r270 top value=4.7uF
C202 "C1608X6S1C475K080AC" 0603L 3215,1895 r270 top value=4.7uF
C203 "C1608X6S1C475K080AC" 0603L 3115,1895 r270 top value=4.7uF
C204 "C1608X6S1C475K080AC" 0603L 3015,1895 r270 top value=4.7uF
C205 "C1608X6S1C475K080AC" 0603L 2915,1895 r270 top value=4.7uF
C206 "C1608X6S1C475K080AC" 0603L 2810,1375 r0 top value=4.7uF
C207 "C1608X6S1C475K080AC" 0603L 2810,1775 r0 top value=4.7uF
C208 "C1608X6S1C475K080AC" 0603L 2810,1475 r0 top value=4.7uF
C209 "C1608X6S1C475K080AC" 0603L 2255,1315 r270 top value=4.7uF
C210 "C1608X6S1C475K080AC" 0603L 2355,1315 r270 top value=4.7uF
C211 "C1608X6S1C475K080AC" 0603L 2405,1315 r270 top value=4.7uF
C212 "C1608X6S1C475K080AC" 0603L 2455,1315 r270 top value=4.7uF
C213 "C1608X6S1C475K080AC" 0603L 2505,1315 r270 top value=4.7uF
C214 "C1608X6S1C475K080AC" 0603L 2810,1725 r0 top value=4.7uF
C215 "C1608X6S1C475K080AC" 0603L 2810,1675 r0 top value=4.7uF
C216 "C1608X6S1C475K080AC" 0603L 3480,2965 r90 top value=4.7uF
C217 "C1608X6S1C475K080AC" 0603L 3800,2155 r0 bottom value=4.7uF
C218 "C1608X6S1C475K080AC" 0603L 3800,2325 r0 bottom value=4.7uF
C219 "C1608X6S1C475K080AC" 0603L 2810,1675 r0 bottom value=4.7uF
C220 "C1608X6S1C475K080AC" 0603L 3415,1895 r270 bottom value=4.7uF
C221 "C1608X6S1C475K080AC" 0603L 3365,1895 r270 bottom value=4.7uF
C222 "C1608X6S1C475K080AC" 0603L 3315,1895 r270 bottom value=4.7uF
C223 "C1608X6S1C475K080AC" 0603L 3465,1895 r270 bottom value=4.7uF
C224 "C1608X6S1C475K080AC" 0603L 3480,2965 r90 bottom value=4.7uF
C225 "C1608X6S1C475K080AC" 0603L 2965,1895 r270 bottom value=4.7uF
C226 "C1608X6S1C475K080AC" 0603L 2915,1895 r270 bottom value=4.7uF
C227 "C1608X6S1C475K080AC" 0603L 2810,1375 r0 bottom value=4.7uF
C228 "C1608X6S1C475K080AC" 0603L 2810,1425 r0 bottom value=4.7uF
C229 "C1608X6S1C475K080AC" 0603L 2810,1575 r0 bottom value=4.7uF
C230 "C1608X6S1C475K080AC" 0603L 3115,1895 r270 bottom value=4.7uF
C231 "C1608X6S1C475K080AC" 0603L 3165,1895 r270 bottom value=4.7uF
C232 "C1608X6S1C475K080AC" 0603L 3215,1895 r270 bottom value=4.7uF
C233 "C1608X6S1C475K080AC" 0603L 3265,1895 r270 bottom value=4.7uF
C234 "C1608X6S1C475K080AC" 0603L 3800,2380 r0 bottom value=4.7uF
C235 "C1608X6S1C475K080AC" 0603L 3800,2520 r0 bottom value=4.7uF
C236 "C1608X6S1C475K080AC" 0603L 3800,2680 r0 bottom value=4.7uF
C237 "C1608X6S1C475K080AC" 0603L 3800,2730 r0 bottom value=4.7uF
C238 "C1608X6S1C475K080AC" 0603L 2810,1575 r0 top value=4.7uF
C239 "C1608X6S1C475K080AC" 0603L 2810,1625 r0 top value=4.7uF
C240 "C1608X6S1C475K080AC" 0603L 2555,1315 r270 top value=4.7uF
C241 "C1608X6S1C475K080AC" 0603L 2865,1895 r270 bottom value=4.7uF
C242 "C1608X6S1C475K080AC" 0603L 2810,1825 r0 bottom value=4.7uF
C243 "C1608X6S1C475K080AC" 0603L 2810,1725 r0 bottom value=4.7uF
C244 "C1608X6S1C475K080AC" 0603L 2810,1775 r0 bottom value=4.7uF
C245 "C1608X6S1C475K080AC" 0603L 2865,1895 r270 top value=4.7uF
C246 "C1608X6S1C475K080AC" 0603L 3615,1895 r270 top value=4.7uF
C247 "C1608X6S1C475K080AC" 0603L 3515,1895 r270 top value=4.7uF
C248 "C1608X6S1C475K080AC" 0603L 3365,1895 r270 top value=4.7uF
C249 "C1608X6S1C475K080AC" 0603L 3515,1895 r270 bottom value=4.7uF
C250 "C1608X6S1C475K080AC" 0603L 3565,1895 r270 bottom value=4.7uF
C251 "C1608X6S1C475K080AC" 0603L 3615,1895 r270 bottom value=4.7uF
C252 "C1608X6S1C475K080AC" 0603L 3665,1895 r270 bottom value=4.7uF
C253 "C1608X6S1C475K080AC" 0603L 3715,1895 r270 bottom value=4.7uF
C254 "C1608X6S1C475K080AC" 0603L 3800,2045 r0 bottom value=4.7uF
C255 "C1608X6S1C475K080AC" 0603L 3800,2100 r0 bottom value=4.7uF
C256 "C1608X6S1C475K080AC" 0603L 3800,2922.64 r0 bottom value=4.7uF
C257 "C1608X6S1C475K080AC" 0603L 2810,1475 r0 bottom value=4.7uF
C258 "C1608X6S1C475K080AC" 0603L 2810,1525 r0 bottom value=4.7uF
C259 "C1608X6S1C475K080AC" 0603L 2810,1625 r0 bottom value=4.7uF
C260 "C1608X6S1C475K080AC" 0603L 2605,1315 r270 top value=4.7uF
C261 "C1608X6S1C475K080AC" 0603L 2655,1315 r270 top value=4.7uF
C262 "C1608X6S1C475K080AC" 0603L 2705,1315 r270 top value=4.7uF
C263 "C1608X6S1C475K080AC" 0603L 2705,1315 r270 bottom value=4.7uF
C264 "C1608X6S1C475K080AC" 0603L 3800,2465 r0 bottom value=4.7uF
C265 "C1608X6S1C475K080AC" 0603L 3800,2575 r0 bottom value=4.7uF
C266 "C1608X6S1C475K080AC" 0603L 3800,2780 r0 bottom value=4.7uF
C267 "C1608X6S1C475K080AC" 0603L 3800,2870 r0 bottom value=4.7uF
C268 "C1608X6S1C475K080AC" 0603L 2140,2965 r90 top value=4.7uF
C269 "C1608X6S1C475K080AC" 0603L 2090,2965 r90 top value=4.7uF
C270 "C1608X6S1C475K080AC" 0603L 2040,2965 r90 top value=4.7uF
C271 "C1608X6S1C475K080AC" 0603L 3065,1895 r270 bottom value=4.7uF
C272 "C1608X6S1C475K080AC" 0603L 3015,1895 r270 bottom value=4.7uF
C273 "C1608X6S1C475K080AC" 0603L 3715,1895 r270 top value=4.7uF
C274 "C1608X6S1C475K080AC" 0603L 3665,1895 r270 top value=4.7uF
C275 "C1608X6S1C475K080AC" 0603L 3565,1895 r270 top value=4.7uF
C276 "C1608X6S1C475K080AC" 0603L 3465,1895 r270 top value=4.7uF
C277 "C1608X6S1C475K080AC" 0603L 3415,1895 r270 top value=4.7uF
C278 "C1608X6S1C475K080AC" 0603L 3265,1895 r270 top value=4.7uF
C279 "C1608X6S1C475K080AC" 0603L 3165,1895 r270 top value=4.7uF
C280 "C1608X6S1C475K080AC" 0603L 3065,1895 r270 top value=4.7uF
C281 "C1608X6S1C475K080AC" 0603L 2965,1895 r270 top value=4.7uF
C282 "C1608X6S1C475K080AC" 0603L 2810,1825 r0 top value=4.7uF
C283 "C1608X6S1C475K080AC" 0603L 2205,1315 r270 top value=4.7uF
C284 "C1608X6S1C475K080AC" 0603L 2810,1525 r0 top value=4.7uF
C285 "C1608X6S1C475K080AC" 0603L 2810,1425 r0 top value=4.7uF
C286 "C1608X6S1C475K080AC" 0603L 2305,1315 r270 top value=4.7uF
C300 "Capacitor" 0603 2314.96,1783.46 r180 bottom value=0.1uF
C319 "Capacitor" 0603 2208.66,2082.68 r90 bottom value=0.1uF
FID1 "Fiducial" Fiducial10-20 440,3520 r0 top
FID2 "Fiducial" Fiducial10-20 640,300 r0 top
FID3 "Fiducial" Fiducial10-20 3490,330 r0 top
H1 "NY PMS 440 0025 PH" "NY PMS 440 0025 PH" 190,3730 r0 top locked
H2 "NY PMS 440 0025 PH" "NY PMS 440 0025 PH" 3760,3760 r0 top locked
H3 "NY PMS 440 0025 PH" "NY PMS 440 0025 PH" 200,200 r0 top locked
H4 "NY PMS 440 0025 PH" "NY PMS 440 0025 PH" 3740,180 r0 top locked
H5 "1902C" Keystone_1902C 190,3730 r180 bottom locked
H6 "1902C" Keystone_1902C 3760,3760 r180 bottom locked
H7 "1902C" Keystone_1902C 200,200 r180 bottom locked
H8 "1902C" Keystone_1902C 3740,180 r180 bottom locked
J101 "Header_2x1" Mill-Max_800-10-002-10-001000 1290,3205 r0 top
J300 "ED120/2DS" On-Shore_ED120_2DS 322.83,1799.21 r270 top
J302 "ED120/4DS" On-Shore_ED120_4DS 3716.54,2527.56 r90 top
J303 "ED120/4DS" On-Shore_ED120_4DS 3724.41,1389.76 r90 top
J304 "800-10-003-10-001000" Mill-Max_800-10-003-10-001000 2433.07,2464.57 r270 top
J309 "U.FL-R-SMT-1(01)" CONN_UFL-R-SMT-1 2330.71,1913.39 r180 bottom
J319 "U.FL-R-SMT-1(01)" CONN_UFL-R-SMT-1 2330.71,2149.61 r90 bottom
L1 "FP1007R3-R30-R" IND_FP1007R3 1945,2345 r0 top value=300nH
L2 "FP1007R3-R30-R" IND_FP1007R3 1945,1585 r0 top value=300nH
LBL1 "THT-14-423-10" Label_650x200 1040,170 r0 top
Logo3 "FCC disclaimer" FCC_disclaimer 1860,3780 r0 top
Q300 "MOSFET_N_D56789G4S123" DQH0008A 2311.02,1464.57 r180 bottom value=25V
R10 "Resistor" 0402 1653.35,2051.18 r90 bottom value=23.7k
R11 "Resistor" 0402 1606.1,2051.18 r90 bottom value=40.2k
R12 "Resistor" 0402 1558.86,2051.18 r90 bottom value=8.66k
R13 "Resistor" 0402 1393.7,2196.85 r180 bottom value=45.3k
R14 "Resistor" 0402 1511.61,2051.18 r270 bottom value=8.66k
R15 "Resistor" 0402 1700.59,2051.18 r270 bottom value=187k
R16 "Resistor" 0805_HV 1660,2655 r0 top value=3.0
R17 "Resistor" 0805_HV 1660,2565 r0 top value=3.0
R19 "Resistor" 0402 1710,2175 r270 top value=0
R21 "Resistor" 0402 1389.76,1523.62 r0 bottom value=45.3k
R23 "Resistor" 0402 1570.87,1397.64 r90 bottom value=40.2k
R24 "Resistor" 0402 1618.11,1397.64 r90 bottom value=51.1k
R25 "Resistor" 0402 1716.54,1393.7 r0 bottom value=187k
R26 "Resistor" 0805_HV 1660,1990 r0 top value=3.0
R27 "Resistor" 0805_HV 1660,1900 r180 top value=3.0
R29 "Resistor" 0402 1705,1485 r270 top value=0
R30 "Resistor" 0402 1393.7,2240.16 r180 bottom value=100k
R31 "Resistor" 0402 1393.7,2287.4 r0 bottom value=0
R41 "Resistor" 0402 1390,1590 r180 bottom value=0
R50 "Resistor" 0402 1751.97,2145.67 r270 bottom value=10
R51 "Resistor" 0402 1803.15,2145.67 r270 bottom value=9.76Meg
R52 "Resistor" 0402 1889.76,2118.11 r180 bottom value=1.00k
R53 "Resistor" 0402 1992.13,2169.29 r180 bottom value=10
R54 "Resistor" 0402 1390,1365 r180 bottom value=0
R55 "Resistor" 0402 1390,1470 r180 bottom value=0
R56 "Resistor" 0402 1390,1415 r180 bottom value=0
R301 "Resistor" 0603 2488.19,1322.83 r270 bottom value=1.00
R302 "Resistor" 0603 2629.92,1326.77 r180 bottom value=10.0k
R303 "Resistor" 2512 2334.65,1669.29 r0 bottom value=0.02
R304 "Resistor" 0402 2433.07,1783.46 r0 bottom value=49.9
R314 "Resistor" 0402 2299.21,2039.37 r180 bottom value=49.9
TP102 "5000" Keystone5000 1080,3210 r90 top
TP103 "5000" Keystone5000 913.39,2968.5 r90 top
TP105 "5000" Keystone5000 2295.28,2555.12 r90 top
TP106 "5000" Keystone5000 2291.34,2409.45 r90 top
TP107 "5002" Keystone5002 2618.11,2570.87 r90 top
TP109 "5001" Keystone5001 1480,3210 r90 top
TP300 "5000" Keystone5000 291.34,2232.28 r90 top
TP301 "5000" Keystone5000 1224.41,2082.68 r90 top
TP302 "5000" Keystone5000 3645.67,3106.3 r90 top
TP303 "5001" Keystone5001 307.09,1472.44 r90 top
TP304 "5001" Keystone5001 3433.07,846.46 r90 top
TP305 "5016" Testpoint_Keystone_Compact 2295.28,2732.28 r0 top
TP307 "5001" Keystone5001 2818.9,1212.6 r90 bottom
TP308 "5016" Testpoint_Keystone_Compact 1208.66,2570.87 r270 top
TP309 "5016" Testpoint_Keystone_Compact 1185.04,1496.06 r180 top
TP310 "5000" Keystone5000 2598.43,1212.6 r180 bottom
TP315 "5016" Testpoint_Keystone_Compact 2283.46,1240.16 r0 bottom
U1 "" RVF0040A 1555,2275 r180 top
U2 "TPS543C20RVFT" RVF0040A 1555,1590 r180 top
ZZ1 "This Assembly Note is for PCB labels only" AssemblyNoteLabel 50,6900 r0 top

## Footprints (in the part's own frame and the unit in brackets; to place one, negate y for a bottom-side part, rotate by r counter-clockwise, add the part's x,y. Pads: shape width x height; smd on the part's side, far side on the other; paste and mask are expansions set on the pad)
0402 [mm] "0402 from SM-752 data"
  rect 0.8x0.6 smd: 1(-0.6,0) 2(0.6,0)
  silkscreen extent -1.22,-0.52 1.22,0.52, body extent -0.55,-0.3 0.55,0.3, height 0.6
0603 [mm] "0603 from SM-752 data"
  rect 1x0.95 smd: 1(-0.8,0) 2(0.8,0)
  silkscreen extent -1.52,-0.69 1.52,0.69, body extent -0.87,-0.47 0.87,0.47, height 1
0603L [mm] "0603 from SM-752 data"
  rect 0.8x0.85 smd: 1(-0.7,0) 2(0.7,0)
  silkscreen extent -0.07,-0.33 0.07,0.33, body extent -0.87,-0.47 0.87,0.47, height 1
0603S [mil]
  rect 20x35 smd: 1(-30,0) 2(30,0)
  body extent -34,-19 34,19, height 39
0805_HV [mil] "0805 with 30mil clearance between pads"
  rect 50x63 smd: 1(-40,0) 2(40,0)
  silkscreen extent -74,-40 74,40, body extent -43,-29 43,29, height 57
1206_190L [mm] "1206_190"
  rect 1.1x1.75 smd: 1(-1.35,0) 2(1.35,0)
  silkscreen extent -0.4,-0.77 0.4,0.77, body extent -1.75,-0.95 1.75,0.95, height 1.9
1210_280 [mm] "SMD, 2-Leads, Body 3.6x2.8mm, Height 2.8mm"
  rect 1.1x2.2 smd: 1(-1.65,0) 2(1.65,0)
  silkscreen extent -0.84,-1.4 0.84,1.4, body extent -1.8,-1.4 1.8,1.4, height 2.8
2512 [mm] "Chip Resistor, Body 6.3x3.2mm, IPC Medium Density"
  rect 1.3x3.4 smd: 1(-2.95,0) 2(2.95,0)
  silkscreen extent -1.9,-1.6 1.9,1.6, body extent -3.22,-1.67 3.22,1.67, height 0.71
AssemblyNoteLabel [mil] "Assembly Note for PCB Labels"
CONN_UFL-R-SMT-1 [mm] "Hirose recommended land pattern http://www.hirose.co.jp/cataloge_hp/e32119372.pdf 2009.2"
  rect 1.05x1 smd paste-0.1 mask-0.1: 1(-1.525,0)
  rect 2.2x1.05 smd paste-2 mask-2: 2(0,1.475) 3(0,-1.475)
  rect 2x0.9 on Bottom Paste: 2(0,1.5) 3(0,-1.5)
  rect 2x0.9 on Bottom Solder: 2(0,1.5) 3(0,-1.5)
  Top Layer keep-out region: -0.8,0.7 1.1,0.7 1.1,-0.7 -0.8,-0.7
  silkscreen extent -1.7,-1.7 1.7,1.7, body extent -1.55,-1.5 1.55,1.5, height 1.27
DQH0008A [mm] "TI"
  rrect39% 0.91x0.51 smd paste-0.05 mask-0.05: 1(-2.795,1.905) 2(-2.795,0.635) 3(-2.795,-0.635) 4(-2.795,-1.905) 5(2.795,-1.905) 6(2.795,-0.635) 7(2.795,0.635) 8(2.795,1.905)
  rrect9% 1.14x1.23 on Bottom Paste: 9(-1.06,-1.43) 9(-1.06,0) 9(-1.06,1.43) 9(0.28,-1.43) 9(0.28,0) 9(0.28,1.43) 9(1.62,-1.43) 9(1.62,0) 9(1.62,1.43)
  rrect2% 4.02x4.42 on Bottom Solder: 9(0.38,0)
  rrect2% 4.93x4.52 smd paste-3 mask-3: 9(0.786,0)
  silkscreen extent -3.18,-2.68 3.18,2.68, body extent -3.05,-2.55 3.05,2.55, height 1.06
FCC_disclaimer [mil]
Fiducial10-20 [mm]
  round 1 smd mask+0.5: 1(0,0)
  Top Layer keep-out circle w1.178: c0,0 r0.5
IND_FP1007R3 [mm] "Coiltronics recommended Rev 0910"
  rect 3x2.5 smd: 1(-3.85,0) 2(3.85,0)
  silkscreen extent -5.3,-4.1 5.3,4.1, body extent -5.2,-4 5.2,4, height 7.5
Keystone5000 [mil] "For Keystone 500x miniature loop terminals"
  round 80 hole 40: 1(0,0)
  silkscreen extent -52,-52 52,52, body extent -49,-49 49,49, height 182
Keystone5001 [mil] "For Keystone 500x miniature loop terminals"
  round 80 hole 40: 1(0,0)
  silkscreen extent -52,-52 52,52, body extent -49,-49 49,49, height 182
Keystone5002 [mil] "For Keystone 500x miniature loop terminals"
  round 80 hole 40: 1(0,0)
  silkscreen extent -52,-52 52,52, body extent -49,-49 49,49, height 182
Keystone_1902C [mil] "Hex Standoff, 4-40 threaded, nylon"
  round 1 on Mech4: 0(0,0)
  body extent -145,-126 146,126, height 501
Label_650x200 [mil] "Thermal Transfer Label"
  round 1 on Mech13: 0(0,0)
  silkscreen extent -325,-100 325,100, body extent -325,-100 325,100, height 1
Mill-Max_800-10-002-10-001000 [mm] "Mill-Max"
  rect 1.5x1.5 hole 0.85: 1(-1.27,0)
  round 1.5 hole 0.85: 2(1.27,0)
  silkscreen extent -2.54,-1.27 2.54,1.78, body extent -2.54,-1.27 2.54,1.27, height 8.13
Mill-Max_800-10-003-10-001000 [mm] "Mill-Max"
  rect 1.5x1.5 hole 0.85: 1(-2.54,0)
  round 1.5 hole 0.85: 2(0,0) 3(2.54,0)
  silkscreen extent -3.81,-1.27 3.81,1.78, body extent -3.81,-1.27 3.81,1.27, height 8.13
"NY PMS 440 0025 PH" [mm] "4-40 nylon screw and mounting hole"
  round 8 hole 3.2: 1(0,0)
  body extent -3.3,-3.3 3.3,3.3, height 2.69
On-Shore_ED120_2DS [mm] "ONSHORE"
  rrect5% 2x2 hole 1.25: 1(-2.54,0)
  round 2 hole 1.25: 2(2.54,0)
  silkscreen extent -5.6,-4 5.12,5, body extent -5.78,-4 5.08,5, height 13
On-Shore_ED120_4DS [mm] "ONSHORE"
  rrect5% 2x2 hole 1.25: 1(-7.62,0)
  round 2 hole 1.25: 2(-2.54,0) 3(2.54,0) 4(7.62,0)
  silkscreen extent -10.68,-4 10.16,5, body extent -10.86,-4 10.16,5, height 13
RVF0040A [mm]
  rrect40% 0.6x0.25 smd: 1(-2.4,2.75) 2(-2.4,2.25) 3(-2.4,1.75) 4(-2.4,1.25) 5(-2.4,0.75) 6(-2.4,0.25) 7(-2.4,-0.25) 8(-2.4,-0.75) 9(-2.4,-1.25) 10(-2.4,-1.75) 11(-2.4,-2.25) 12(-2.4,-2.75) 21(2.4,-2.75) 22(2.4,-2.25) 23(2.4,-1.75) 24(2.4,-1.25) 25(2.4,-0.75) 26(2.4,-0.25) 27(2.4,0.25) 28(2.4,0.75) 29(2.4,1.25) 30(2.4,1.75) 31(2.4,2.25) 32(2.4,2.75)
  rrect40% 0.25x0.6 smd: 13(-1.75,-3.4) 14(-1.25,-3.4) 15(-0.75,-3.4) 16(-0.25,-3.4) 17(0.25,-3.4) 18(0.75,-3.4) 19(1.25,-3.4) 20(1.75,-3.4) 33(1.75,3.4) 34(1.25,3.4) 35(0.75,3.4) 36(0.25,3.4) 37(-0.25,3.4) 38(-0.75,3.4) 39(-1.25,3.4) 40(-1.75,3.4)
  rrect9% 1.43x1.08 on Top Paste: 41(-0.815,1.92) 41(-0.815,-0.64) 41(-0.815,0.64) 41(-0.815,-1.92) 41(0.815,1.92) 41(0.815,-0.64) 41(0.815,0.64) 41(0.815,-1.92)
  rrect3% 3.3x5.3 smd paste-2: 41(0,0)
  silkscreen extent -2.7,-3.7 2.7,3.7, body extent -2.5,-3.5 2.5,3.5, height 1.52
SM_RADIAL_G [mm] "10 x 10.2mm:  Panasonic G"
  rect 4.1x2 smd: 1(-4.35,0) 2(4.35,0)
  silkscreen extent -5.35,-5.35 5.35,5.35, body extent -5.25,-5.25 5.25,5.25, height 10.5
SP-Cap_Standard [mm] "Recommended land pattern for standard Panasonic SP-CAP capacitors"
  rect 2.4x2.8 smd: 1(-3.2,0) 2(3.2,0)
  silkscreen extent -4.25,-2.34 3.75,2.34, body extent -3.75,-2.25 3.75,2.25, height 2.11
Testpoint_Keystone_Compact [mil] "Compact SMT test point"
  rect 185x135 smd: 1(0,0)
  silkscreen extent -110,-80 110,80, body extent -75,-56 75,56, height 91

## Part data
C10 C20: library part CMP-0007870-2, "CAP, CERM, 4.7 uF, 25 V, +/- 10%, X7R, 0805", Cap_Case=0805, Manufacturer=TDK, PartNumber=C2012X7R1E475K125AB, Supplier Part Number 1=445-5972-1-ND, TempCo=X7R, Tolerance_%=10%, Value1=Unknown, Value2=25V, ValueDisplayed=4.7uF
C11 C21: library part CMP-0006764-4, "CAP, CERM, 1000 pF, 50 V, +/- 10%, C0G/NP0, 0603", Cap_Case=0603, Manufacturer=AVX, PartNumber=06035A102KAT2A, Supplier Part Number 1=478-3718-1-ND, TempCo=C0G/NP0, Tolerance_%=10%, Value1="0.048 ohm", Value2=50V, ValueDisplayed=1000pF
C12 C22: library part CMP-0006720-2, "CAP, CERM, 0.1 uF, 25 V, +/- 20%, X7R, 0402", Cap_Case=0402, Manufacturer="Taiyo Yuden", PartNumber=TMK105B7104MV-FR, TempCo=X7R, Tolerance_%=20%, Value1=Unknown, Value2=25V, ValueDisplayed=0.1uF
C13 C23: library part CMP-0007040-4, "CAP, CERM, 1 uF, 25 V, +/- 10%, X7R, 0603", Cap_Case=0603, Manufacturer=TDK, PartNumber=C1608X7R1E105K080AB, Supplier Part Number 1=445-5956-1-ND, TempCo=X7R, Tolerance_%=10%, Value1=Unknown, Value2=25V, ValueDisplayed=1uF
C14 C15 C16 C24 C25 C26: library part CMP-0009117-1, "CAP, CERM, 10 uF, 25 V, +/- 20%, X7R, 1210", Cap_Case=1210, Manufacturer=TDK, PartNumber=C3225X7R1E106M250AC, Supplier Part Number 1=445-1434-1-ND, TempCo=X7R, Tolerance_%=20%, Value1=Unknown, Value2=25V, ValueDisplayed=10uF
C17 C27: library part CMP-0007404-4, "CAP, CERM, 0.1 uF, 25 V, +/- 10%, X7R, 0603", Cap_Case=0603, Manufacturer=MuRata, PartNumber=GRM188R71E104KA01D, Supplier Part Number 1=490-1524-1-ND, TempCo=X7R, Tolerance_%=10%, Value1=Unknown, Value2=25V, ValueDisplayed=0.1uF
C50 C51 C52 C56 C91 C92 C93 C94: library part CMP-0012257-3, "CAP, Aluminum Polymer, 470 uF, 2.5 V, +/- 20%, 4.5 ohm, 7.3x1.8x4.3mm SMD", Manufacturer=Panasonic, PartNumber=EEFSX0E471E4, Supplier Part Number 1=PCE5042CT-ND, Tolerance_%=20%, Value1="4.5 ohm", Value2=2.5V, ValueDisplayed=470uF
C53 C54 C55: library part CMP-0009110-2, "CAP, CERM, 100 uF, 6.3 V, +/- 20%, X6S, 1210", Cap_Case=1210_280, Manufacturer=TDK, PartNumber=C3225X6S0J107M250AC, Supplier Part Number 1=445-6016-1-ND, TempCo=X6S, Tolerance_%=20%, Value1="0.005496 ohm", Value2=6.3V, ValueDisplayed=100uF
C100 C101: library part CMP-0010657-1, "CAP, AL, 330 uF, 25 V, +/- 20%, 0.15 ohm, SMD", Cap_Case=G, Manufacturer=Panasonic, PartNumber=EEE-FC1E331P, Supplier Part Number 1=PCE4007CT-ND, Tolerance_%=20%, Value1="0.15 ohm", Value2=25V, ValueDisplayed=330uF
C102 C103 C104 C105 C106 C107 C108 C109 C110 C111 C112 C113 C114 C115 C116 C117 C118 C119 C120 C121 C122 C123 C124 C125 C126 C127 C128 C129 C130 C131 C132 C133 C134 C135 C136 C137: library part CMP-0064957-2, "CAP, CERM, 100 uF, 6.3 V,+/- 20%, X5R, 1206", Cap_Case=1206, Manufacturer=TDK, Supplier Part Number 1=445-6008-1-ND, TempCo=X5R, Tolerance_%=20%, Value1=Unknown, Value2=6.3V, ValueDisplayed=100uF
C201 C202 C203 C204 C205 C206 C207 C208 C209 C210 C211 C212 C213 C214 C215 C216 C217 C218 C219 C220 C221 C222 C223 C224 C225 C226 C227 C228 C229 C230 C231 C232 C233 C234 C235 C236 C237 C238 C239 C240 C241 C242 C243 C244 C245 C246 C247 C248 C249 C250 C251 C252 C253 C254 C255 C256 C257 C258 C259 C260 C261 C262 C263 C264 C265 C266 C267 C268 C269 C270 C271 C272 C273 C274 C275 C276 C277 C278 C279 C280 C281 C282 C283 C284 C285 C286: library part CMP-0007028-4, "CAP, CERM, 4.7 uF, 16 V, +/- 10%, X6S, 0603", Cap_Case=0603, Manufacturer=TDK, Supplier Part Number 1=445-9118-1-ND, TempCo=X6S, Tolerance_%=10%, Value1="0.003728 ohm", Value2=16V, ValueDisplayed=4.7uF
C300 C319: library part CMP-0006981-4, "CAP, CERM, 0.1 uF, 10 V, +/- 10%, X7R, 0603", Cap_Case=0603, Manufacturer=Kemet, PartNumber=C0603X104K8RACTU, Supplier Part Number 1=399-5343-1-ND, TempCo=X7R, Tolerance_%=10%, Value1=Unknown, Value2=10V, ValueDisplayed=0.1uF
FID1 FID2 FID3: library part CMP-0077181-1, "Fiducial mark.  There is nothing to buy or mount.", Manufacturer=N/A
H1 H2 H3 H4: library part CMP-0003617-1, "Machine Screw, Round, #4-40 x 1/4, Nylon, Philips panhead", Manufacturer="B&F Fastener Supply", Supplier Part Number 1=H542-ND
H5 H6 H7 H8: library part CMP-0003610-1, "Standoff, Hex, 0.5\"L #4-40 Nylon", Manufacturer=Keystone, Supplier Part Number 1=36-1902C-ND
J101: library part CMP-0055085-1, "Header, 100mil, 2x1, TH", Manufacturer=Mill-Max, PartNumber=800-10-002-10-001000, Supplier Part Number 1=ED7202-ND
J300: library part CMP-0074910-1, "Terminal Block, 5.08 mm, 2x1, Brass, TH", Color=Blue, Current_A=15A, Manufacturer="On-Shore Technology", Supplier Part Number 1=ED1609-ND, Voltage_V=300V
J302 J303: library part CMP-0074939-1, "Terminal Block, 5.08 mm, 4x1, Brass, TH", Color=Blue, Current_A=15A, Manufacturer="On-Shore Technology", Supplier Part Number 1=ED2227-ND, Voltage_V=300V
J304: library part CMP-0055086-1, "Header, 100mil, 3x1, TH", Manufacturer=Mill-Max, Supplier Part Number 1=ED7203-ND
J309 J319: library part CMP-0075320-1, "Receptacle, Ultra Miniature Coaxial, Male Pin, 50 ohm, SMT", Color=Beige, Manufacturer="Hirose Electric Co. Ltd.", Supplier Part Number 1=H122041-ND
L1 L2: library part CMP-0058393-1, "Inductor, Wirewound, Ferrite, 300 nH, 35 A, 0.00029 ohm, SMD", Manufacturer=Coiltronics, Supplier Part Number 1=513-1650-1-ND, Value1="0.00029 ohm", Value2=35A, ValueDisplayed=300nH
LBL1: library part CMP-0003625-1, "Thermal Transfer Printable Labels, 0.650\" W x 0.200\" H - 10,000 per roll", Manufacturer=Brady, Supplier Part Number 1=97C5133
Logo3: library part CMP-0074847-1, "FCC_disclaimer"
Q300: library part CMP-0000264-1, "MOSFET, N-CH, 25 V, 113 A, DQH0008A (VSON-CLIP-8)", Alternate Manufacturer=None, Manufacturer="Texas Instruments", PartNumber=CSD16408Q5, Supplier Part Number 1=296-25321-1-ND, Value1=0.005, Value2="6.7 nC"
R10: library part CMP-0026683-1, "RES, 23.7 k, 1%, 0.1 W, AEC-Q200 Grade 0, 0402", Manufacturer=Panasonic, PartNumber=ERJ-2RKF2372X, Power_W=100mW, Supplier Part Number 1=P23.7KLCT-ND, TempCo="100 ppm/C", Tolerance_%=1%, Value2=0.1W, Value_Code=23k7, ValueDisplayed=23.7k
R11 R23: library part CMP-0026367-2, "RES, 40.2 k, 1%, 0.063 W, AEC-Q200 Grade 0, 0402", Manufacturer=Vishay-Dale, PartNumber=CRCW040240K2FKED, Power_W=63mW, Supplier Part Number 1=541-40.2KLCT-ND, TempCo="100 ppm/C", Tolerance_%=1%, Value2=0.063W, Value_Code=40k2, ValueDisplayed=40.2k
R12 R14: library part CMP-0026591-2, "RES, 8.66 k, 1%, 0.063 W, AEC-Q200 Grade 0, 0402", Manufacturer=Vishay-Dale, PartNumber=CRCW04028K66FKED, Power_W=63mW, Supplier Part Number 1=541-8.66KLCT-ND, TempCo="100 ppm/C", Tolerance_%=1%, Value2=0.063W, Value_Code=8k66, ValueDisplayed=8.66k
R13 R21: library part CMP-0026387-2, "RES, 45.3 k, 1%, 0.063 W, AEC-Q200 Grade 0, 0402", Manufacturer=Vishay-Dale, PartNumber=CRCW040245K3FKED, Power_W=63mW, Supplier Part Number 1=541-45.3KLCT-ND, TempCo="100 ppm/C", Tolerance_%=1%, Value2=0.063W, Value_Code=45k3, ValueDisplayed=45.3k
R15 R25: library part CMP-0026056-3, "RES, 187 k, 1%, 0.063 W, AEC-Q200 Grade 0, 0402", Manufacturer=Vishay-Dale, PartNumber=CRCW0402187KFKED, Power_W=63mW, Supplier Part Number 1=541-187KLCT-ND, TempCo="100 ppm/C", Tolerance_%=1%, Value2=0.063W, Value_Code=187k
R16 R17 R26 R27: library part CMP-0020820-2, "RES, 3.0, 5%, 0.125 W, 0805", Manufacturer="Yageo America", PartNumber=RC0805JR-073RL, Power_W=125mW, Supplier Part Number 1=311-3.0ARCT-ND, TempCo="200 ppm/C", Tolerance_%=5%, Value2=0.125W, Value_Code=3R00, ValueDisplayed=3.0
R19 R29 R31 R41 R54 R55 R56: library part CMP-0026822-3, "RES, 0, 5%, 0.063 W, AEC-Q200 Grade 0, 0402", Manufacturer=Vishay-Dale, PartNumber=CRCW04020000Z0ED, Power_W=63mW, Supplier Part Number 1=541-0.0JCT-ND, TempCo="200 ppm/C", Tolerance_%=5%, Value2=0.063W, Value_Code=0000, ValueDisplayed=0
R24: library part CMP-0026437-2, "RES, 51.1 k, 1%, 0.063 W, AEC-Q200 Grade 0, 0402", Manufacturer=Vishay-Dale, PartNumber=CRCW040251K1FKED, Power_W=63mW, Supplier Part Number 1=541-51.1KLCT-ND, TempCo="100 ppm/C", Tolerance_%=1%, Value2=0.063W, Value_Code=51k1, ValueDisplayed=51.1k
R30: library part CMP-0026823-3, "RES, 100 k, 5%, 0.063 W, AEC-Q200 Grade 0, 0402", Manufacturer=Vishay-Dale, PartNumber=CRCW0402100KJNED, Power_W=63mW, Supplier Part Number 1=541-100KJCT-ND, TempCo="200 ppm/C", Tolerance_%=5%, Value2=0.063W, Value_Code=100k
R50 R53: library part CMP-0026827-3, "RES, 10, 5%, 0.063 W, AEC-Q200 Grade 0, 0402", Manufacturer=Vishay-Dale, PartNumber=CRCW040210R0JNED, Power_W=63mW, Supplier Part Number 1=541-10JCT-ND, TempCo="200 ppm/C", Tolerance_%=5%, Value2=0.063W, Value_Code=10R0, ValueDisplayed=10
R51: library part CMP-0026626-3, "RES, 9.76 M, 1%, 0.063 W, AEC-Q200 Grade 0, 0402", Manufacturer=Vishay-Dale, PartNumber=CRCW04029M76FKED, Power_W=63mW, Supplier Part Number 1=71-CRCW04029M76FKED, TempCo="100 ppm/C", Tolerance_%=1%, Value2=0.063W, Value_Code=9M76, ValueDisplayed=9.76M
R52: library part CMP-0026071-3, "RES, 1.00 k, 1%, 0.063 W, AEC-Q200 Grade 0, 0402", Manufacturer=Vishay-Dale, PartNumber=CRCW04021K00FKED, Power_W=63mW, Supplier Part Number 1=541-1.00KLCT-ND, TempCo="100 ppm/C", Tolerance_%=1%, Value2=0.063W, Value_Code=1k00, ValueDisplayed=1.00k
R301: library part CMP-0022170-4, "RES, 1.00, 1%, 0.1 W, AEC-Q200 Grade 0, 0603", Manufacturer=Vishay-Dale, PartNumber=CRCW06031R00FKEA, Power_W=100mW, Supplier Part Number 1=52K8059, TempCo="100 ppm/C", Tolerance_%=1%, Value2=0.1W, Value_Code=1R00, ValueDisplayed=1.00
R302: library part CMP-0023341-3, "RES, 10.0 k, 1%, 0.1 W, AEC-Q200 Grade 0, 0603", Manufacturer="Stackpole Electronics Inc", PartNumber=RMCF0603FT10K0, Power_W=100mW, Supplier Part Number 1=RMCF0603FT10K0CT-ND, TempCo="100 ppm/C", Tolerance_%=1%, Value2=0.1W, Value_Code=10k0, ValueDisplayed=10.0k
R303: library part CMP-0015420-2, "RES, 0.02, 1%, 3 W, 2512", Manufacturer=Bourns, PartNumber=CRA2512-FZ-R020ELF, Power_W=3W, Supplier Part Number 1=CRA2512-FZ-R020ELFCT-ND, TempCo="75 ppm/C", Tolerance_%=1%, Value_Code=R020, ValueDisplayed=0.02
R304 R314: library part CMP-0026404-2, "RES, 49.9, 1%, 0.063 W, AEC-Q200 Grade 0, 0402", Manufacturer=Vishay-Dale, PartNumber=CRCW040249R9FKED, Power_W=63mW, Supplier Part Number 1=541-49.9LCT-ND, TempCo="100 ppm/C", Tolerance_%=1%, Value2=0.063W, Value_Code=49R9, ValueDisplayed=49.9
TP102 TP103 TP105 TP106 TP300 TP301 TP302 TP310: library part CMP-0055137-1, "Test Point, Miniature, Red, TH", Color=Red, Manufacturer=Keystone, Supplier Part Number 1=36-5000-ND
TP107: library part CMP-0055139-1, "Test Point, Miniature, White, TH", Color=White, Manufacturer=Keystone, Supplier Part Number 1=36-5002-ND
TP109 TP303 TP304 TP307: library part CMP-0055138-1, "Test Point, Miniature, Black, TH", Color=Black, Manufacturer=Keystone, Supplier Part Number 1=36-5001-ND
TP305 TP308 TP309 TP315: library part CMP-0055153-1, "Test Point, Compact, SMT", Manufacturer=Keystone, Supplier Part Number 1=36-5016TR-ND
U1: library part CMP-0014070-7, "4-16Vin 40A Stackable Synchronous Step-down SWIFT(TM) Converter w/ Adaptive Internal Compensation, RVF0040A (LQFN-CLIP-40)", Alternate Manufacturer="Texas Instruments", Alternate PartNumber=TPS543C20RVFR, Operating Temperature Range="-40 to 125 C", PartNumber=TPS543C20RVFT, Rating=Catalog
U2: library part CMP-0014070-7, "4-16Vin 40A Stackable Synchronous Step-down SWIFT(TM) Converter w/ Adaptive Internal Compensation, RVF0040A (LQFN-CLIP-40)", Alternate Manufacturer="Texas Instruments", Alternate PartNumber=TPS543C20RVFR, Operating Temperature Range="-40 to 125 C", Rating=Catalog
ZZ1: library part CMP-0003616-3

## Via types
v1: diameter 22, hole 10, Top Layer to Bottom Layer, tented both sides, 317 vias
v2: diameter 22, hole 10, Top Layer to Bottom Layer, 72 vias
v3: diameter 19.68, hole 7.87, Top Layer to Bottom Layer, 32 vias

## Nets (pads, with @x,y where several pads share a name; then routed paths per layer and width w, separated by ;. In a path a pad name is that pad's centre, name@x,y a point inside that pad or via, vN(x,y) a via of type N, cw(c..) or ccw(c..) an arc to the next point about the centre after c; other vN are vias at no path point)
BP1_5V: C20.1 U2.28 | length 91.9
  Top Layer w9: C20.1@1380.86,1530.86 1410.47,1560.47 1435.47,1560.47 U2.28@1460.51,1560.47
  other v1: 1435,1560
BP2_5V: C10.2 R30.1 U1.28 | length 108.7
  Top Layer w9: C10.2@1380,2210 1410,2240 v1(1433,2240) 1438.47,2245.47 U1.28@1460.51,2245.47 U1.28@1460.04,2245
  Bottom Layer w20: R30.1@1417.32,2240.16 R30.1@1430.16,2240.16
Enable: J101.1 TP102.1 U1.33 U2.33 | length 2566.9
  Top Layer w9: v1(1340,2120) 1460,2120 1468.82,2128.82 1468.82,2134.95 1473.86,2140 1484.96,2140 U1.33@1486.1,2141.14 ; v1@1486.1,1426.1 U2.33@1486.1,1456.14
  Top Layer w10: v1@1486.1,1426.1 1490,1422.2 v1(1490,1420)
  Top Layer w30: TP102.1@1080,3210 1085,3205 J101.1@1240,3205
  Signal Layer 2 w10: J101.1@1240,3205 1240,2680 1232.54,2672.54 1232.54,2487.46 1240,2480 1240,2220 v1(1340,2120) 1340,2080.4 1381.52,2038.87 1394.89,2038.87 1408.87,2024.89 1408.87,2024.71 1410,2023.58 1410,1805 1355,1750 1355,1515.28 1320,1480.28 1320,1355 1336.42,1338.58 1453.58,1338.58 1490,1375 v1(1490,1420)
